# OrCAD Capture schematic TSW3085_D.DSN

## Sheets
1 SH2 - DAC PWR: size B; title: TSW3085 EVM; rev: D; note: DAC PWR
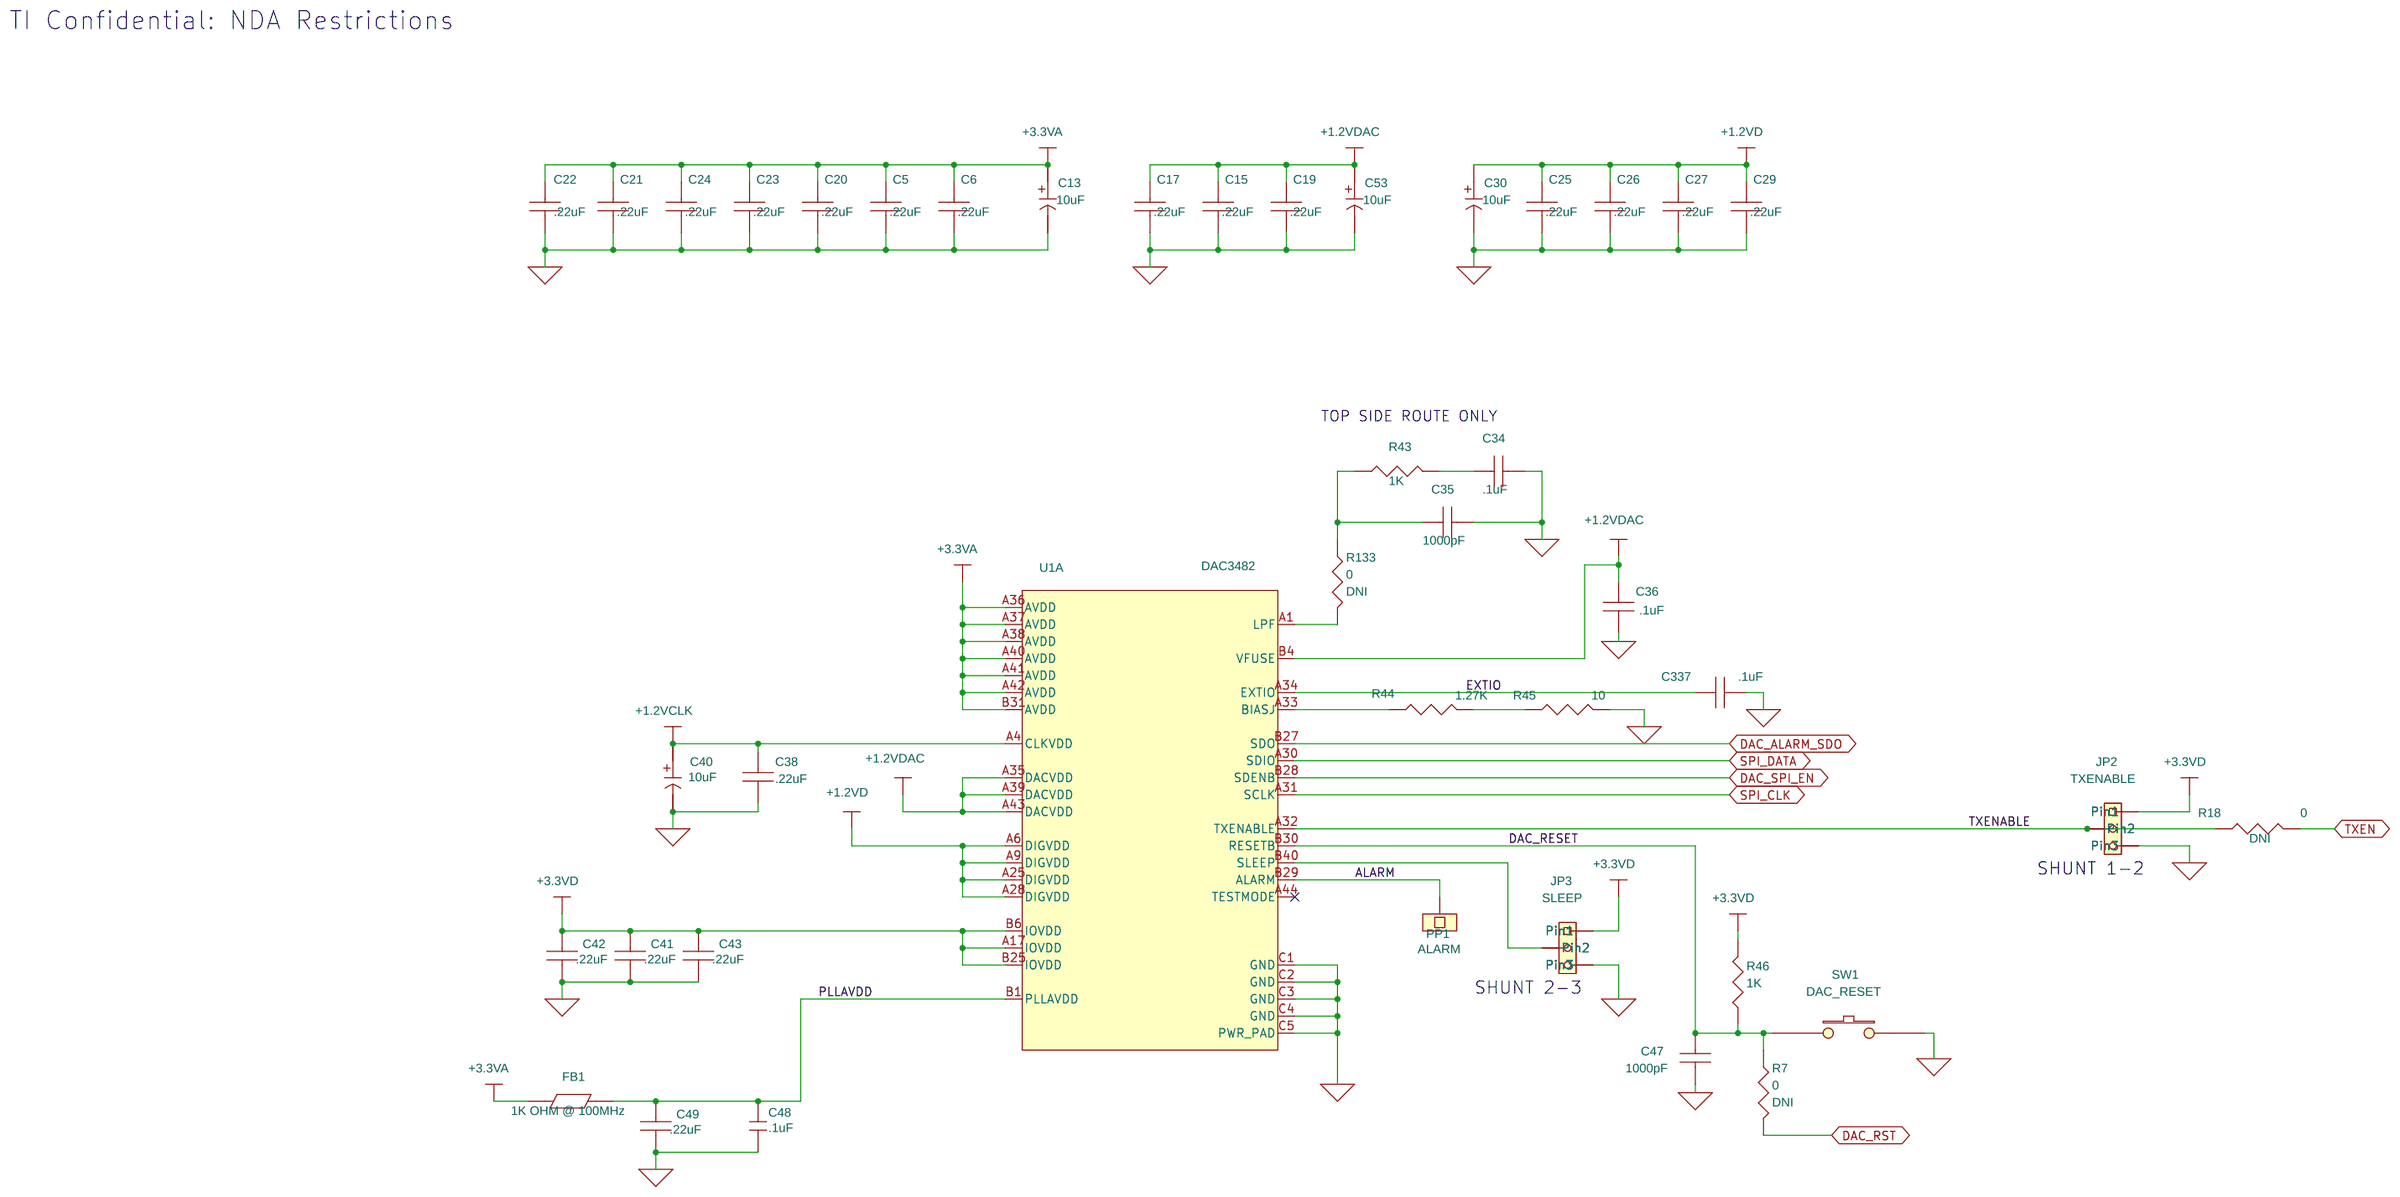
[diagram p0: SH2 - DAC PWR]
2 SH3 - CLOCK: size B; note: CLOCK
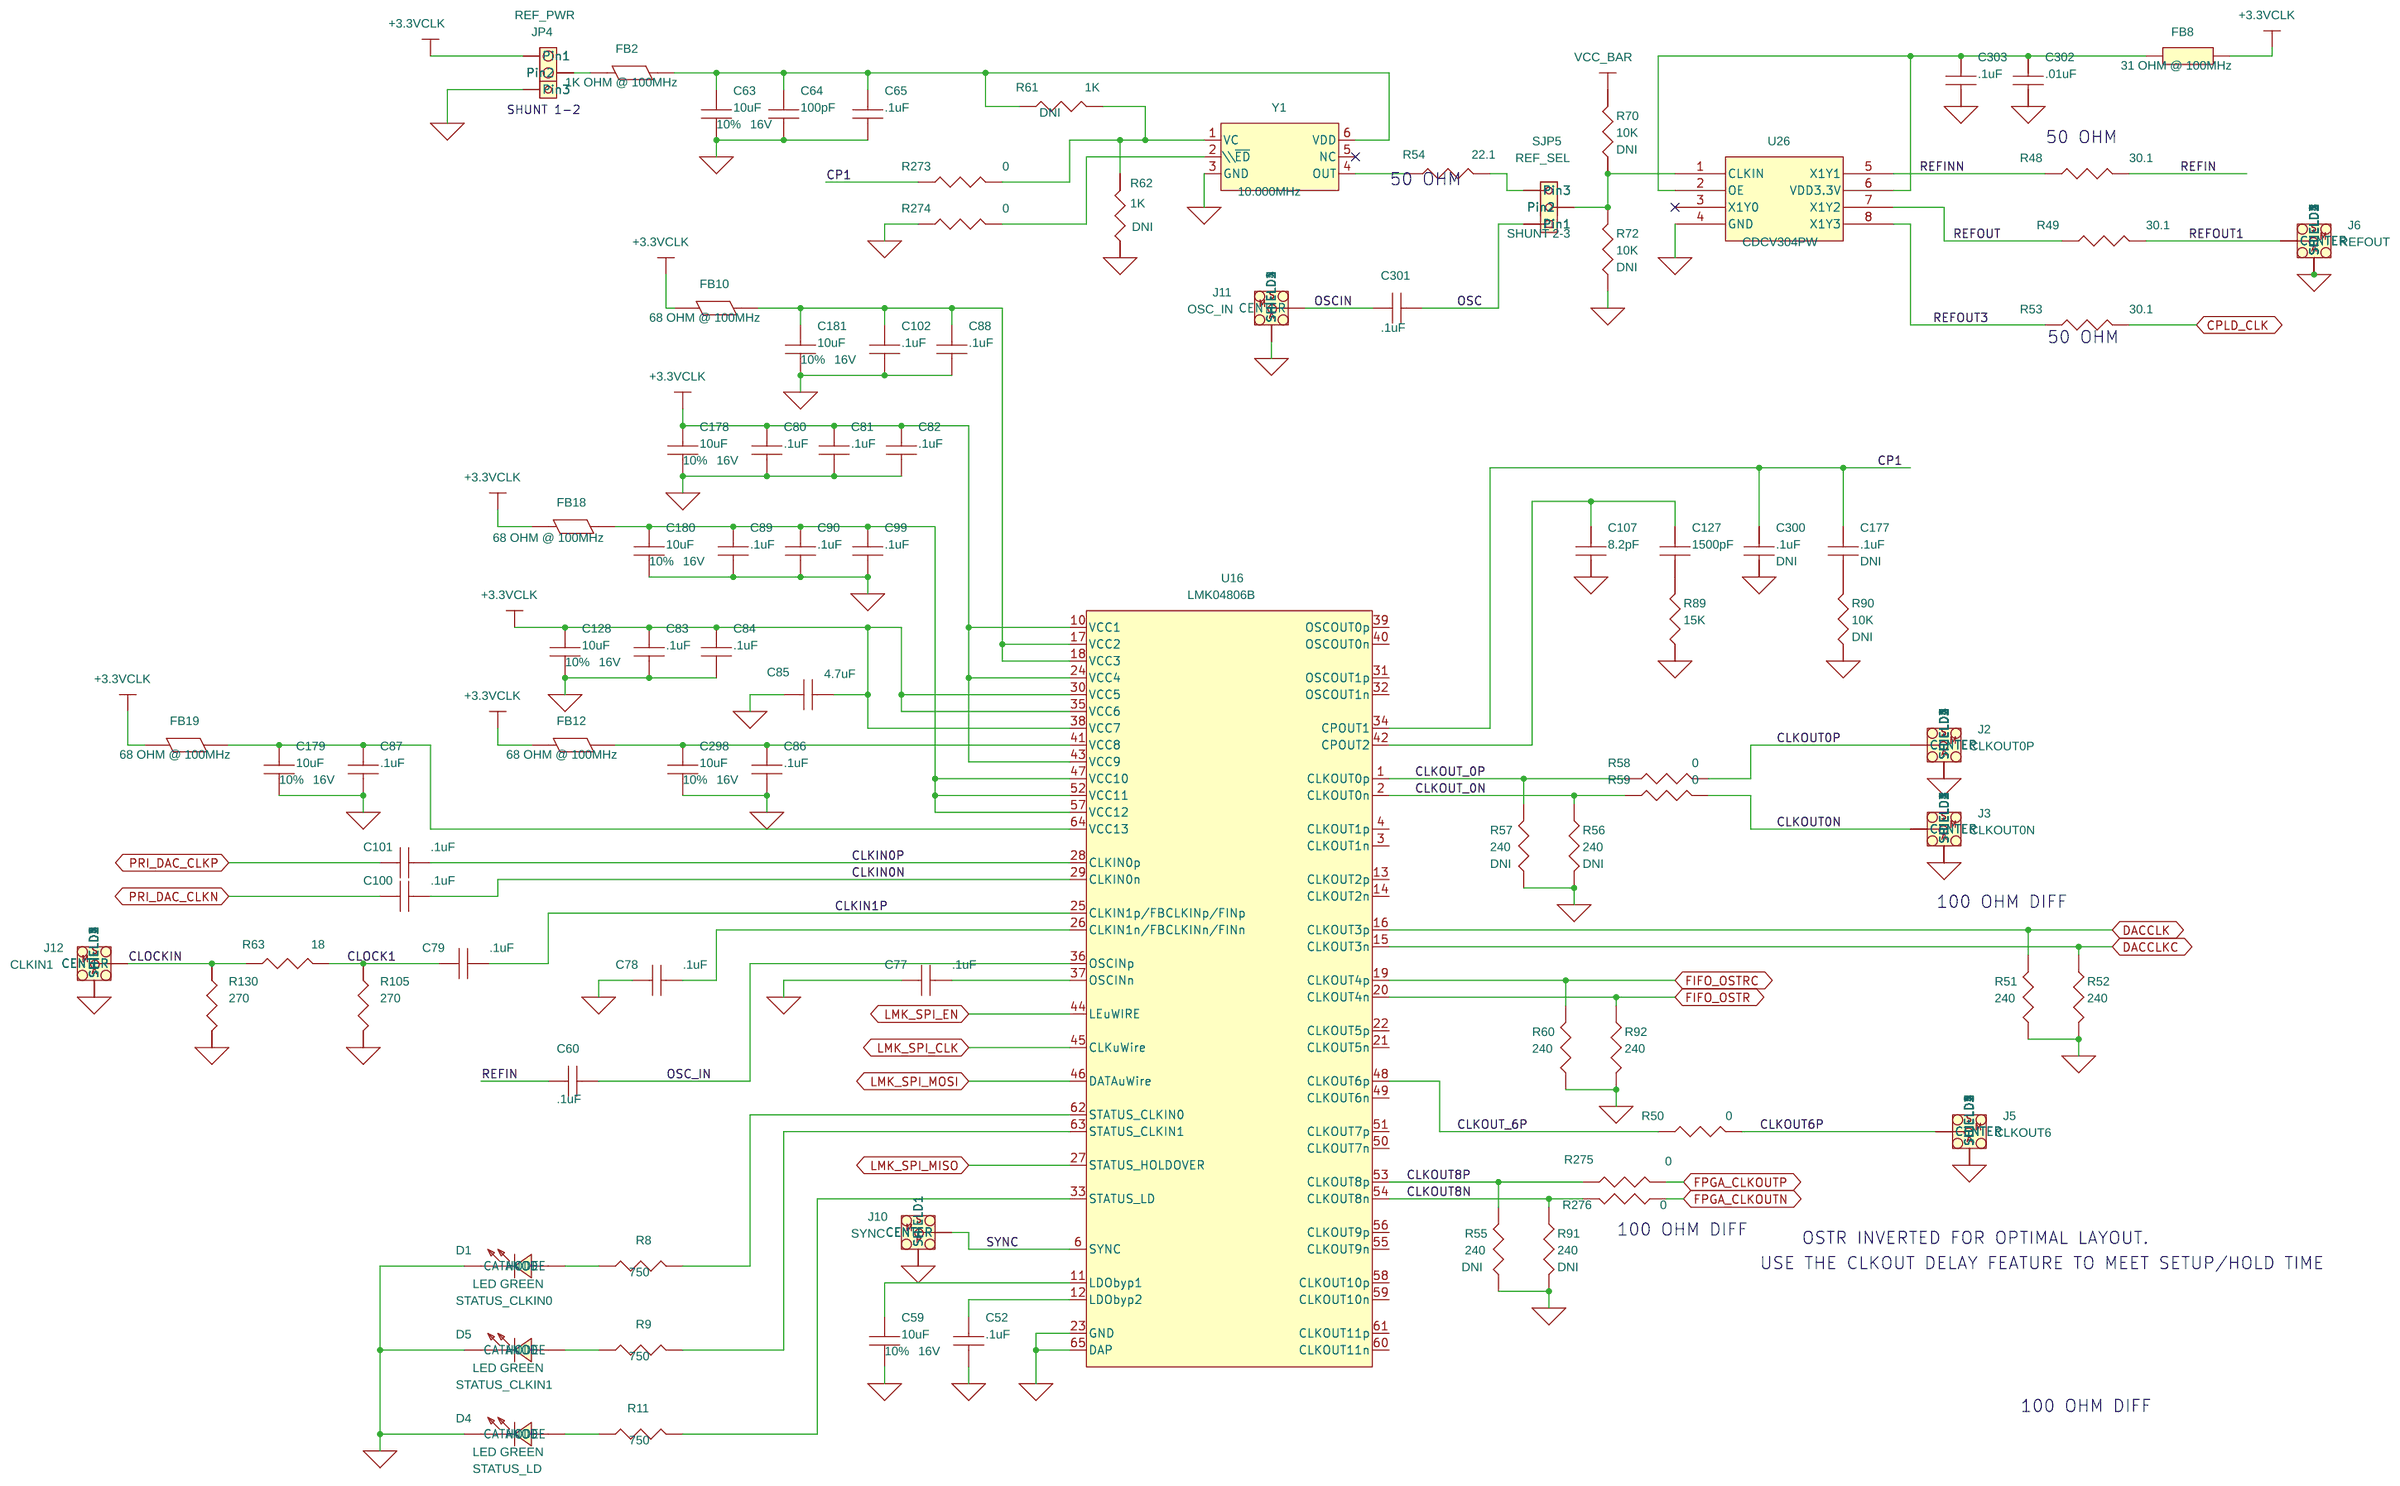
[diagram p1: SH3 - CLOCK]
3 SH5 - TX AMP & ATTENUATORS: size B; note: TX AMPLIFIER AND ATTENUATORS
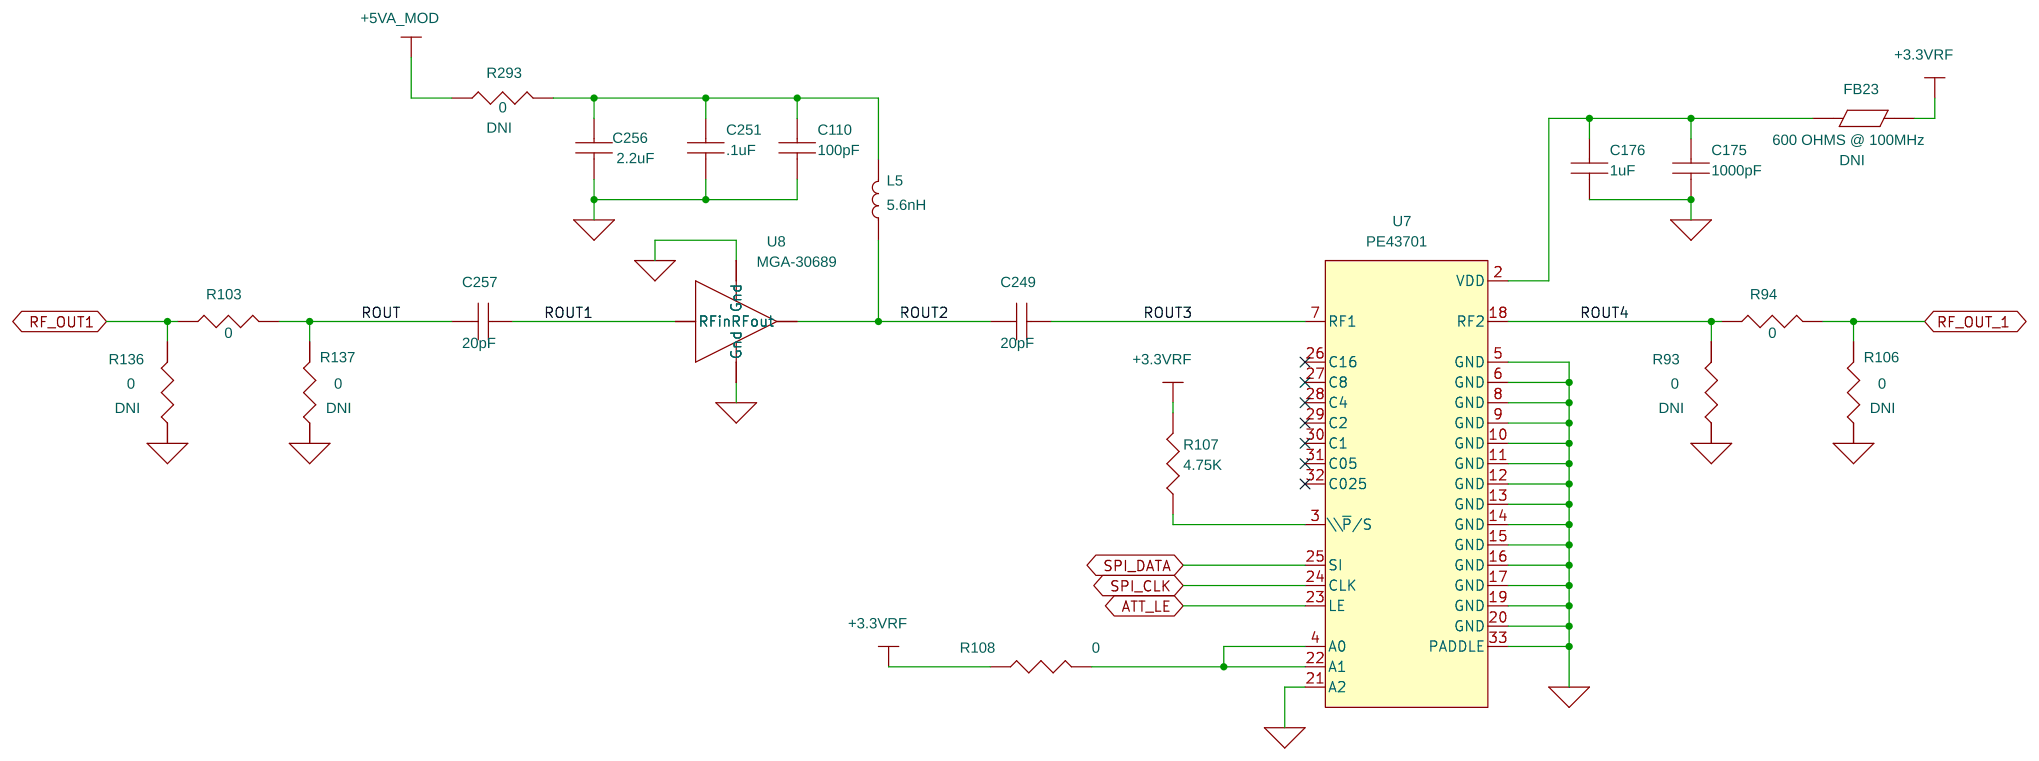
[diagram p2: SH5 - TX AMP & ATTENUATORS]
4 SH1 - DAC: size B; note: DAC
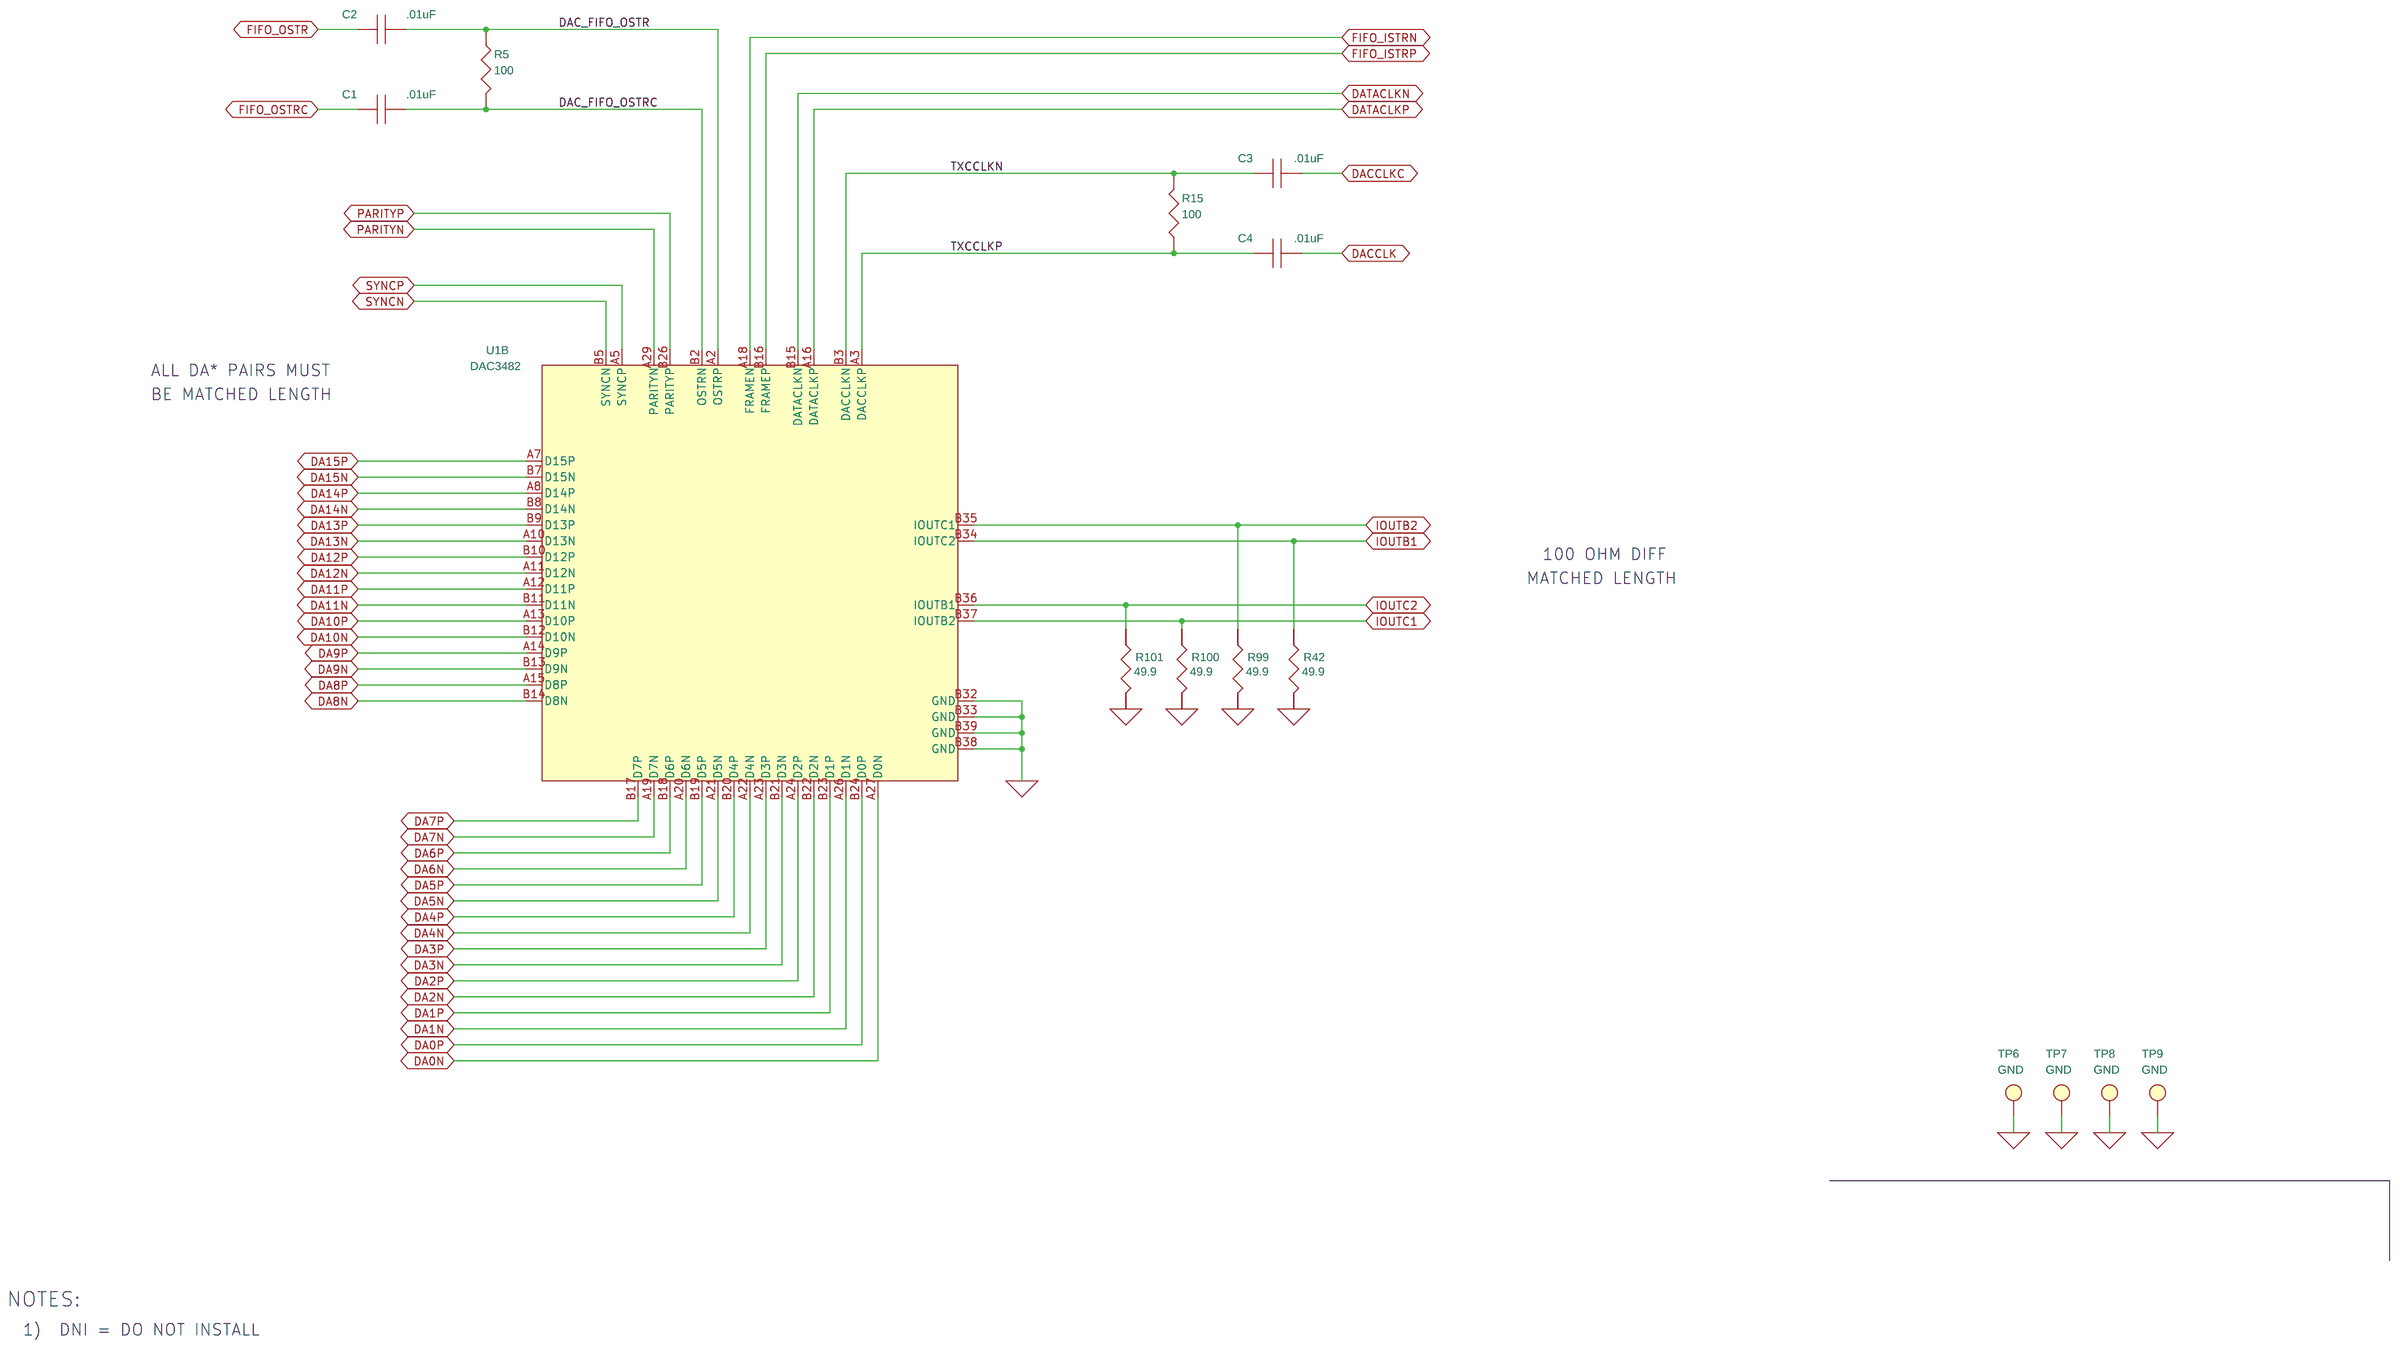
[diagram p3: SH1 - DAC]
5 SH4 - MODULATOR: size B; note: MODULATOR
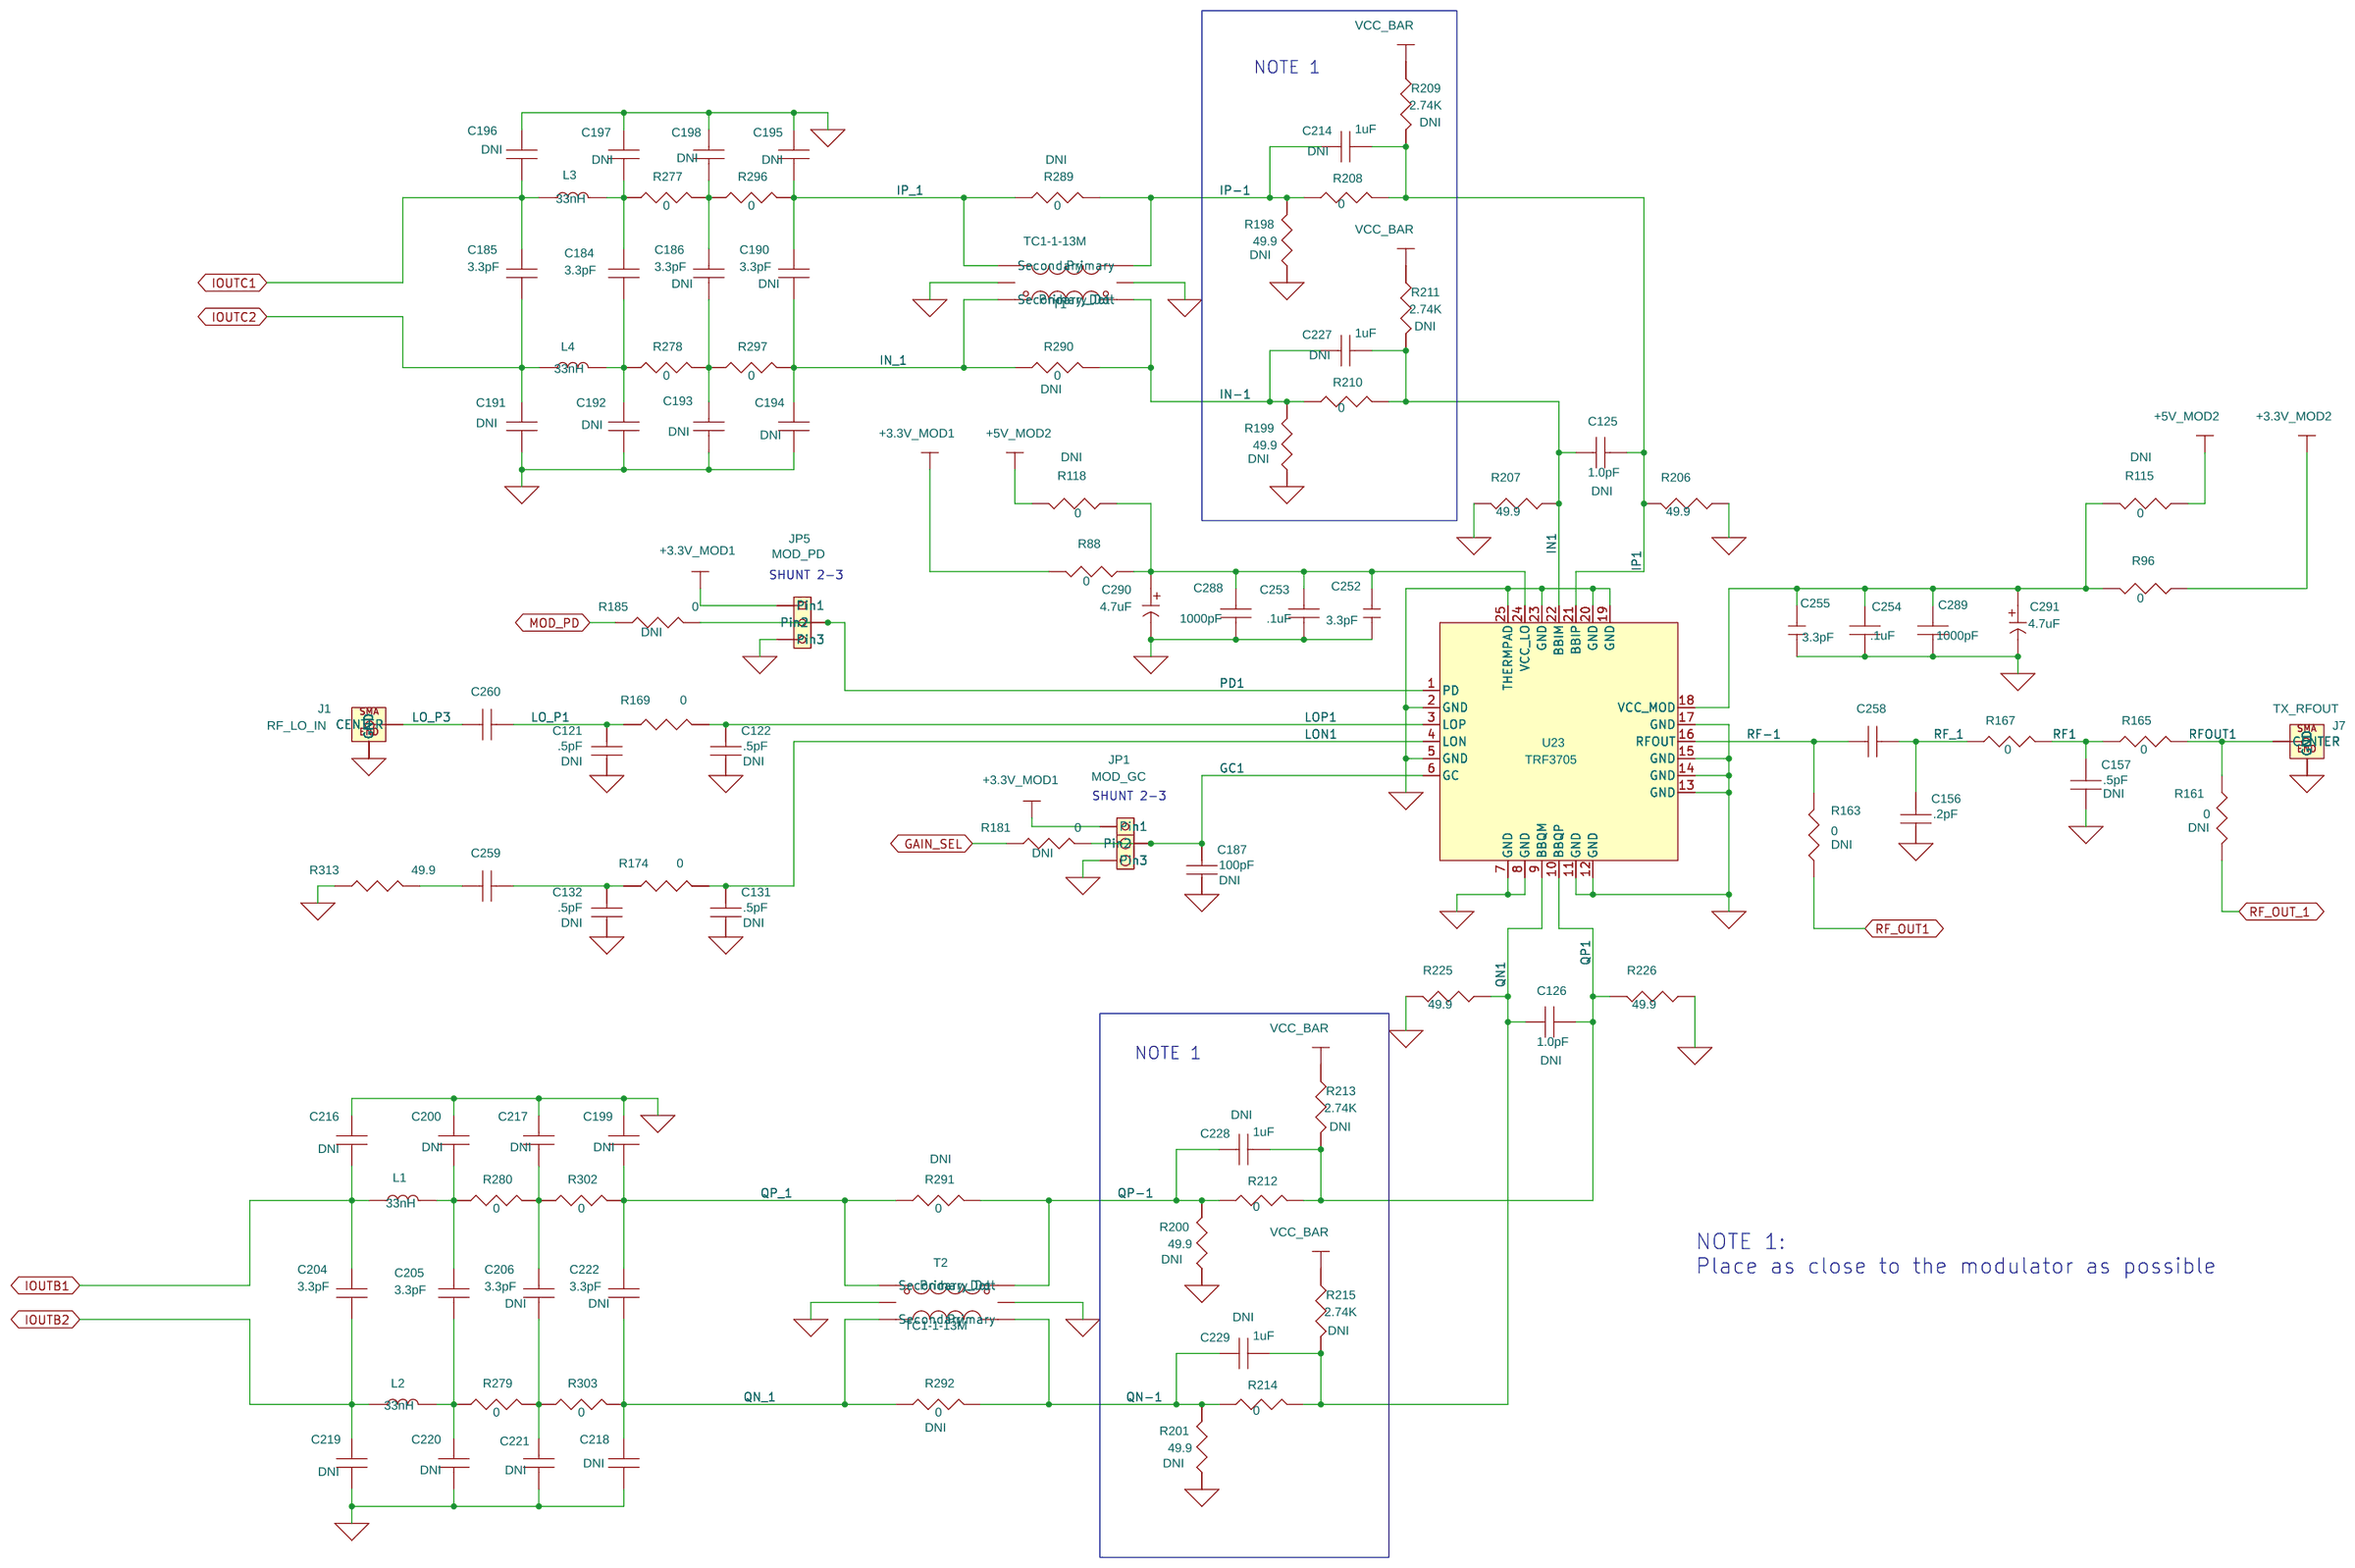
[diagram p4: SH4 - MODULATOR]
6 SH6 - INTERFACE CONTROL: size B; note: INTERFACE
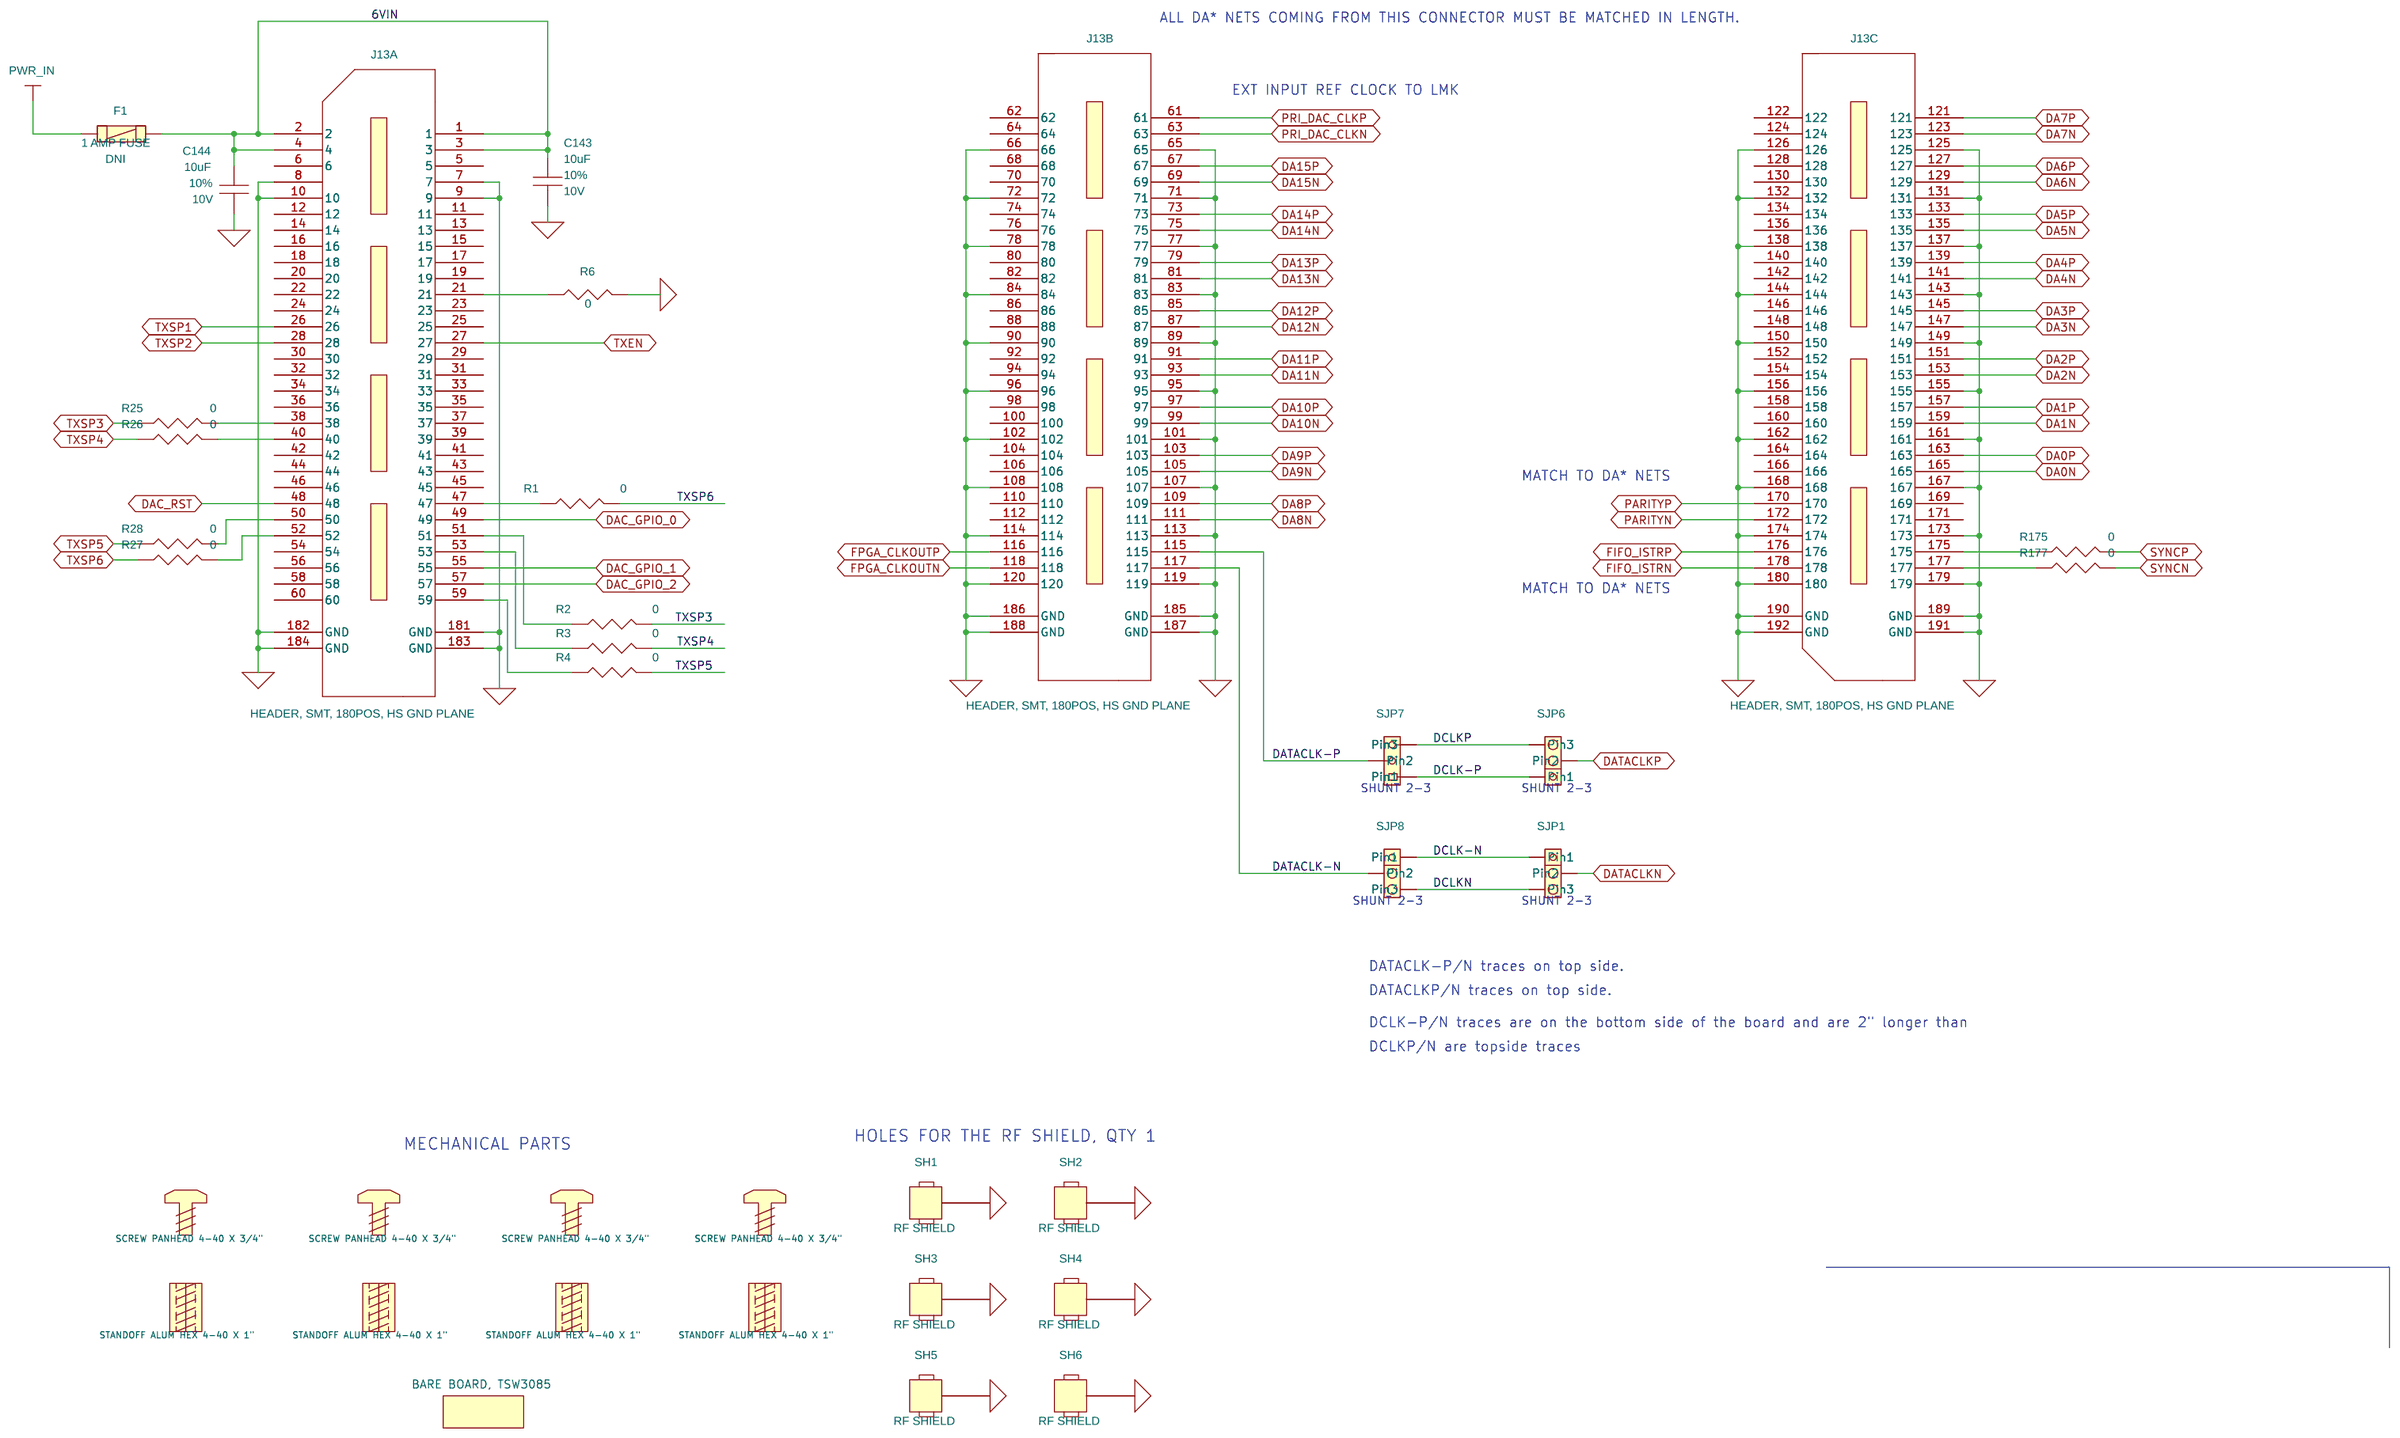
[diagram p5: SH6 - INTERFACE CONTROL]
7 SH7 - USB INTERFACE: size B; note: USB
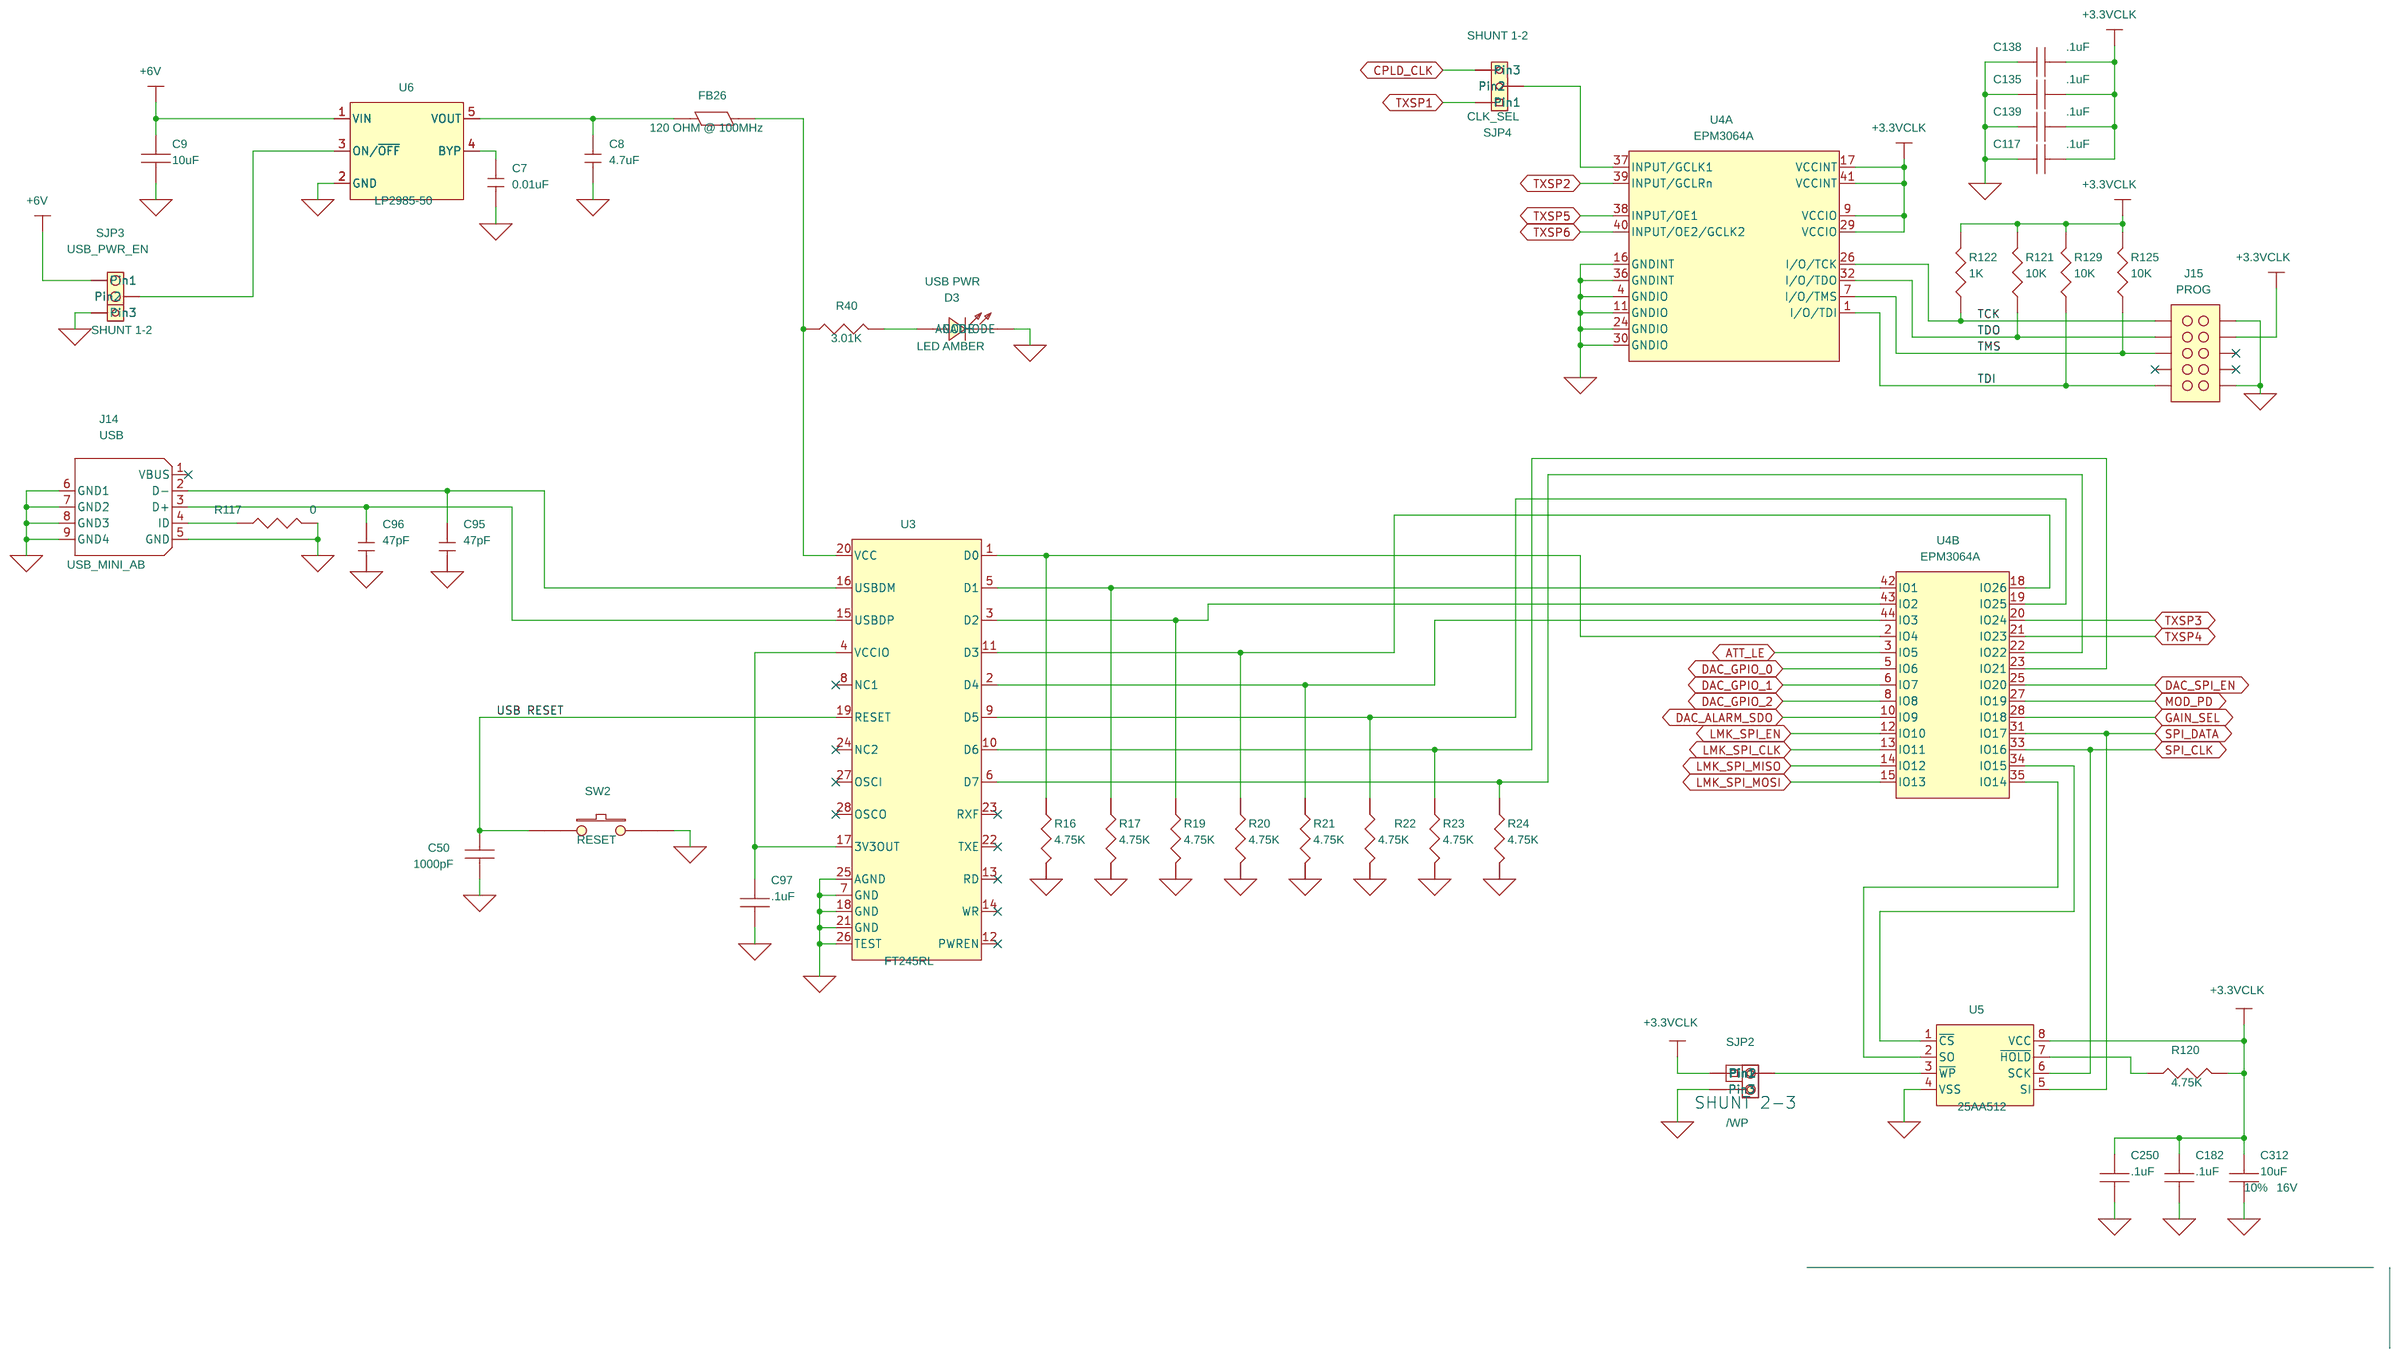
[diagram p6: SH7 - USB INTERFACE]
8 SH8 - POWER DISTRIBUTION: size B; note: DAC
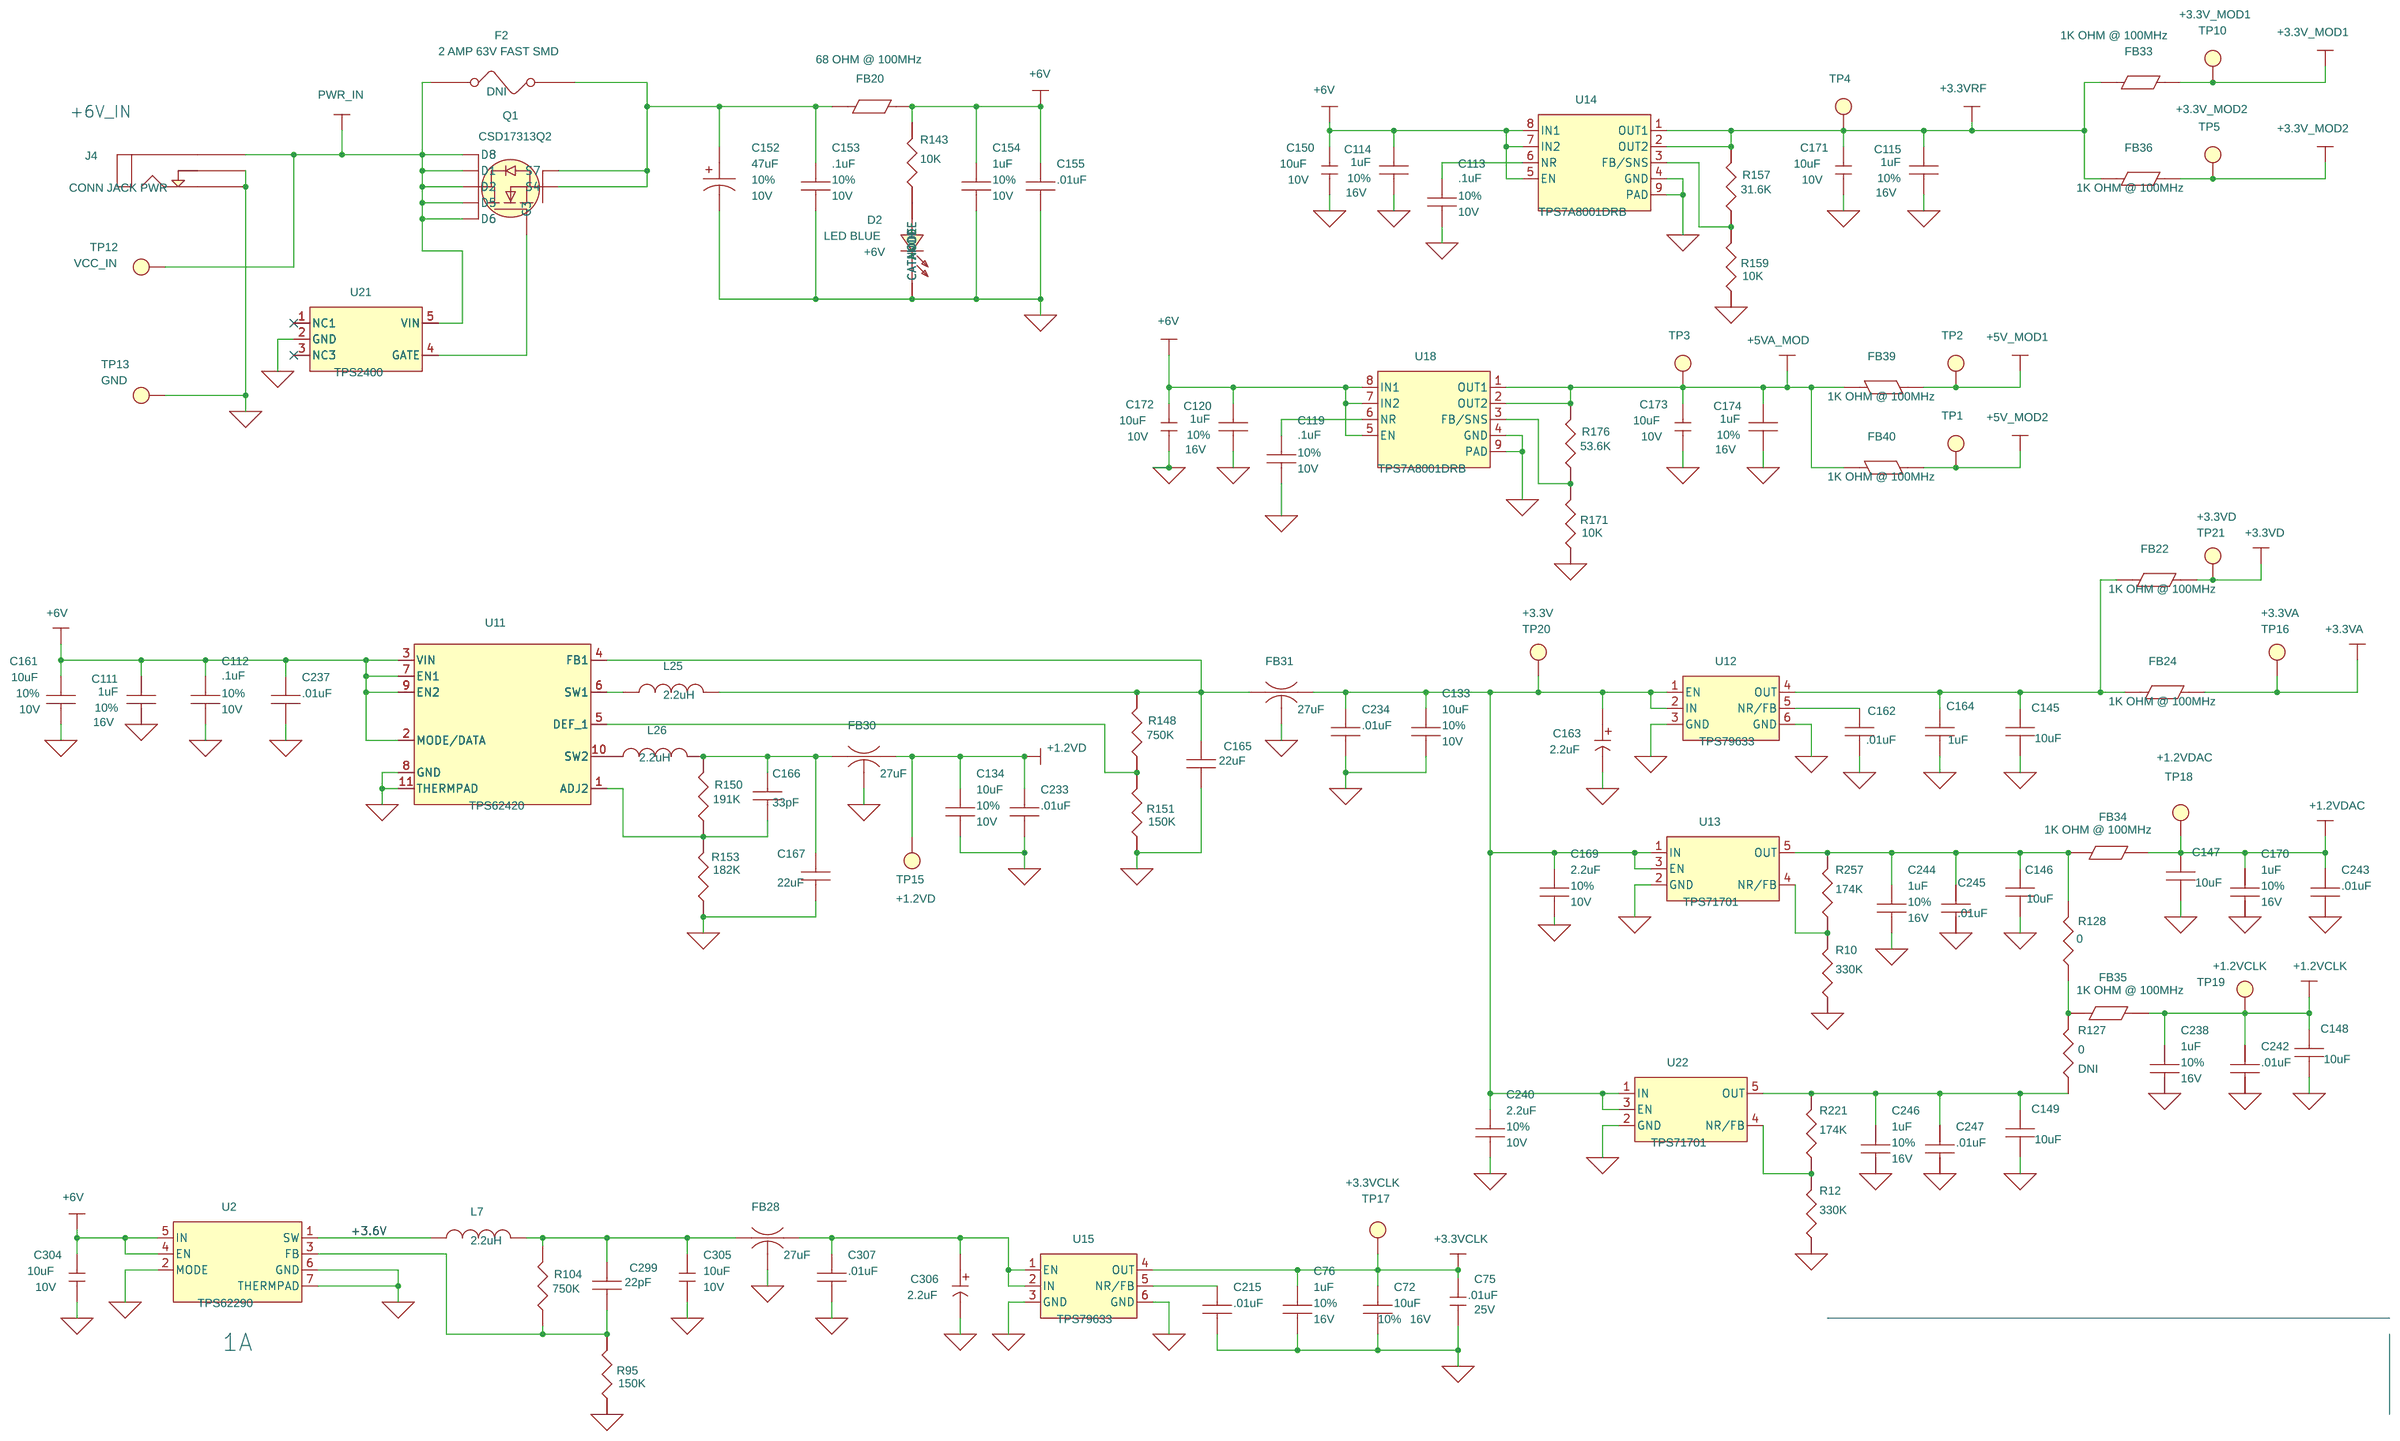
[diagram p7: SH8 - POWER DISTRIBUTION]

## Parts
sheet SH1 - DAC
C1  .01uF  [0402]
C2  .01uF  [0402]
C3  .01uF  [0402]
C4  .01uF  [0402]
R5  100  [0402]
R15  100  [0402]
R42  49.9  [0201]
R99  49.9  [0201]
R100  49.9  [0201]
R101  49.9  [0201]
TP6  TEST POINT, BLK  [testpoint_62dia]
TP7  TEST POINT, BLK  [testpoint_62dia]
TP8  TEST POINT, BLK  [testpoint_62dia]
TP9  TEST POINT, BLK  [testpoint_62dia]
U1  DAC3482  [WQFN_88_354X354_0P60MM]  (sections A,B)
sheet SH2 - DAC PWR
C5  .22uF  [0201]
C6  .22uF  [0201]
C13  10uF  [TANT_A]
C15  .22uF  [0201]
C17  .22uF  [0201]
C19  .22uF  [0201]
C20  .22uF  [0201]
C21  .22uF  [0201]
C22  .22uF  [0201]
C23  .22uF  [0201]
C24  .22uF  [0201]
C25  .22uF  [0201]
C26  .22uF  [0201]
C27  .22uF  [0201]
C29  .22uF  [0201]
C30  10uF  [TANT_A]
C34  .1uF  [0402]
C35  1000pF  [0402]
C36  .1uF  [0402]
C38  .22uF  [0201]
C40  10uF  [TANT_A]
C41  .22uF  [0201]
C42  .22uF  [0201]
C43  .22uF  [0201]
C47  1000pF  [0402]
C48  .1uF  [0201]
C49  .22uF  [0201]
C53  10uF  [TANT_A]
C337  .1uF  [0402]
FB1  1K OHM @ 100MHz  [1806]
JP2  HEADER, 3POS  [HDR_THVT_1x3_100_M]
JP3  HEADER, 3POS  [HDR_THVT_1x3_100_M]
PP1  PROBE POINT  [PROBE_POINT_30PAD]
R7  0  [0402]
R18  0  [0402]
R43  1K  [0402]
R44  1.27K  [0402]
R45  10  [0402]
R46  1K  [0402]
R133  0  [0402]
SW1  SW PUSHBUTTON  [SW_RESET_PTS635]
Z_SH-H2  SHUNT-HEADER
Z_SH-H3  SHUNT-HEADER
sheet SH3 - CLOCK
C52  .1uF  [0402]
C59  10uF  [0805]
C60  .1uF  [0402]
C63  10uF  [1206]
C64  100pF  [0402]
C65  .1uF  [0402]
C77  .1uF  [0402]
C78  .1uF  [0402]
C79  .1uF  [0402]
C80  .1uF  [0402]
C81  .1uF  [0402]
C82  .1uF  [0402]
C83  .1uF  [0402]
C84  .1uF  [0402]
C85  4.7uF  [0402]
C86  .1uF  [0402]
C87  .1uF  [0402]
C88  .1uF  [0402]
C89  .1uF  [0402]
C90  .1uF  [0402]
C99  .1uF  [0402]
C100  .1uF  [0402]
C101  .1uF  [0402]
C102  .1uF  [0402]
C107  8.2pF  [0402]
C127  1500pF  [0402]
C128  10uF  [1206]
C177  .1uF  [0402]
C178  10uF  [1206]
C179  10uF  [1206]
C180  10uF  [1206]
C181  10uF  [1206]
C298  10uF  [1206]
C300  .1uF  [0402]
C301  .1uF  [0402]
C302  .01uF  [0402]
C303  .1uF  [0402]
D1  LED GREEN  [LED_0805]
D4  LED GREEN  [LED_0805]
D5  LED GREEN  [LED_0805]
FB2  1K OHM @ 100MHz  [1806]
FB8  31 OHM @ 100MHz  [0805]
FB10  68 OHM @ 100MHz  [1206]
FB12  68 OHM @ 100MHz  [1206]
FB18  68 OHM @ 100MHz  [1206]
FB19  68 OHM @ 100MHz  [1206]
J2  SMA THRU HOLE R/A  [SMA_THRT_276X276]
J3  SMA THRU HOLE R/A  [SMA_THRT_276X276]
J5  SMA THRU HOLE R/A  [SMA_THRT_276X276]
J6  SMA THRU HOLE R/A  [SMA_THRT_276X276]
J10  SMP_PCB_SMT  [smp_b120]
J11  SMA THRU HOLE R/A  [SMA_THRT_276X276]
J12  SMA THRU HOLE  [SMA_THVT_320x320]
JP4  HEADER, 3POS  [HDR_THVT_1x3_100_M]
R8  750  [0603]
R9  750  [0603]
R11  750  [0603]
R48  30.1  [0402]
R49  30.1  [0402]
R50  0  [0402]
R51  240  [0402]
R52  240  [0402]
R53  30.1  [0201]
R54  22.1  [0402]
R55  240  [0402]
R56  240  [0402]
R57  240  [0402]
R58  0  [0402]
R59  0  [0402]
R60  240  [0402]
R61  1K  [0402]
R62  1K  [0402]
R63  18  [0402]
R70  10K  [0402]
R72  10K  [0402]
R89  15K  [0402]
R90  10K  [0402]
R91  240  [0402]
R92  240  [0402]
R105  270  [0402]
R130  270  [0402]
R273  0  [0402]
R274  0  [0402]
R275  0  [0402]
R276  0  [0402]
SJP5  SOLDER JUMPER, 0402  [SMD_JUMPER_L_0402]
U16  LMK04806B  [QFN_64_360X360_0P50MM_SQA64]
U26  CDCV304PW  [TSSOP_8_177x122_26]
Y1  10.000MHz  [OSC_6_SM_295X205_100_CUSTOM]
Z_SH-H4  SHUNT-HEADER
Z_SH-J31  SHUNT-JUMPER-0402
sheet SH4 - MODULATOR
C121  .5pF  [0402]
C122  .5pF  [0402]
C125  1.0pF  [0402]
C126  1.0pF  [0402]
C131  .5pF  [0402]
C132  .5pF  [0402]
C156  .2pF  [0402]
C157  .5pF  [0402]
C184  3.3pF  [0402]
C185  3.3pF  [0402]
C186  3.3pF  [0402]
C187  100pF  [0402]
C190  3.3pF  [0402]
C191  CAP NP_1  [0402]
C192  CAP NP_1  [0402]
C193  CAP NP_1  [0402]
C194  CAP NP_1  [0402]
C195  CAP NP_1  [0402]
C196  CAP NP_1  [0402]
C197  CAP NP_1  [0402]
C198  CAP NP_1  [0402]
C199  CAP NP_1  [0402]
C200  CAP NP_1  [0402]
C204  3.3pF  [0402]
C205  3.3pF  [0402]
C206  3.3pF  [0402]
C214  1uF  [0402]
C216  CAP NP_1  [0402]
C217  CAP NP_1  [0402]
C218  CAP NP_1  [0402]
C219  CAP NP_1  [0402]
C220  CAP NP_1  [0402]
C221  CAP NP_1  [0402]
C222  3.3pF  [0402]
C227  1uF  [0402]
C228  1uF  [0402]
C229  1uF  [0402]
C252  3.3pF  [0402]
C253  .1uF  [0402]
C254  .1uF  [0402]
C255  3.3pF  [0402]
C258  6.8pF  [0402]
C259  47pF  [0402]
C260  47pF  [0402]
C288  1000pF  [0402]
C289  1000pF  [0402]
C290  4.7uF  [tant_a]
C291  4.7uF  [tant_a]
J1  SMA END LAUNCH  [SMA_SMEL_DUAL_PSF-S01_250x215]
J7  SMA END LAUNCH  [SMA_SMEL_DUAL_PSF-S01_250x215]
JP1  HEADER, 3POS  [HDR_THVT_1x3_100_M]
JP5  HEADER, 3POS  [HDR_THVT_1x3_100_M]
L1  33nH  [0402]
L2  33nH  [0402]
L3  33nH  [0402]
L4  33nH  [0402]
R88  0  [0603]
R96  0  [0603]
R115  0  [0603]
R118  0  [0603]
R161  0  [0402]
R163  0  [0402]
R165  0  [0402]
R167  0  [0402]
R169  0  [0402]
R174  0  [0402]
R181  0  [0402]
R185  0  [0402]
R198  49.9  [0402]
R199  49.9  [0402]
R200  49.9  [0402]
R201  49.9  [0402]
R206  49.9  [0402]
R207  49.9  [0402]
R208  0  [0402]
R209  2.74K  [0402]
R210  0  [0402]
R211  2.74K  [0402]
R212  0  [0402]
R213  2.74K  [0402]
R214  0  [0402]
R215  2.74K  [0402]
R225  49.9  [0402]
R226  49.9  [0402]
R277  0  [0402]
R278  0  [0402]
R279  0  [0402]
R280  0  [0402]
R289  0  [0603]
R290  0  [0603]
R291  0  [0603]
R292  0  [0603]
R296  0  [0402]
R297  0  [0402]
R302  0  [0402]
R303  0  [0402]
R313  49.9  [0402]
T1  TC1-1-13M  [XFMR_MINICIRCUITS_AT224_1]
T2  TC1-1-13M  [XFMR_MINICIRCUITS_AT224_1]
U23  TRF3705  [QFN_24_163x163_0p50mm_pwrpad]
Z_SH-H14  SHUNT-HEADER
Z_SH-H16  SHUNT-HEADER
sheet SH5 - TX AMP & ATTENUATORS
C110  100pF  [0402]
C175  1000pF  [0402]
C176  1uF  [0603]
C249  20pF  [0402]
C251  .1uF  [0402]
C256  2.2uF  [0805]
C257  20pF  [0402]
FB23  600 OHMS @ 100MHz  [0603]
L5  5.6nH  [0402]
R93  0  [0402]
R94  0  [0402]
R103  0  [0402]
R106  0  [0402]
R107  4.75K  [0402]
R108  0  [0402]
R136  0  [0402]
R137  0  [0402]
R293  0  [0603]
U7  PE43701  [QFN_32_197X197_20_PWRPAD]
U8  MGA-30689  [SOT_89_4321]
sheet SH6 - INTERFACE CONTROL
C143  10uF  [0805]
C144  10uF  [0805]
F1  1 AMP FUSE  [NANO_SMF]
J13  HEADER, SMT, 180POS, HS GND PLANE  [CON_SMVT_180POS_QTH_SAMTEC_RT1]  (sections A,B,C)
R1  0  [0402]
R2  0  [0402]
R3  0  [0402]
R4  0  [0402]
R6  0  [0402]
R25  0  [0402]
R26  0  [0402]
R27  0  [0402]
R28  0  [0402]
R175  0  [0402]
R177  0  [0402]
SH1  RF SHIELD  [MFG053_PTH]
SH2  RF SHIELD  [MFG053_PTH]
SH3  RF SHIELD  [MFG053_PTH]
SH4  RF SHIELD  [MFG053_PTH]
SH5  RF SHIELD  [MFG053_PTH]
SH6  RF SHIELD  [MFG053_PTH]
SJP1  SOLDER JUMPER, 0603  [JUMPER_SMD_3POS_0402]
SJP6  SOLDER JUMPER, 0603  [JUMPER_SMD_3POS_0402]
SJP7  SOLDER JUMPER, 0603  [JUMPER_SMD_3POS_0402]
SJP8  SOLDER JUMPER, 0603  [JUMPER_SMD_3POS_0402]
Z_BOARD1  BARE BOARD, TSW3085
Z_SCREW1  SCREW PANHEAD 4-40 X 3/4"
Z_SCREW2  SCREW PANHEAD 4-40 X 3/4"
Z_SCREW3  SCREW PANHEAD 4-40 X 3/4"
Z_SCREW4  SCREW PANHEAD 4-40 X 3/4"
Z_SH-H17  SHUNT-JUMPER-0603
Z_SH-H18  SHUNT-JUMPER-0603
Z_SH-H19  SHUNT-JUMPER-0603
Z_SH-H20  SHUNT-JUMPER-0603
Z_STANDOFF1  STANDOFF ALUM HEX 4-40 X 1"
Z_STANDOFF2  STANDOFF ALUM HEX 4-40 X 1"
Z_STANDOFF3  STANDOFF ALUM HEX 4-40 X 1"
Z_STANDOFF4  STANDOFF ALUM HEX 4-40 X 1"
sheet SH7 - USB INTERFACE
C7  0.01uF  [0603]
C8  4.7uF  [0603]
C9  10uF  [0805]
C50  1000pF  [0402]
C95  47pF  [0402]
C96  47pF  [0402]
C97  .1uF  [0402]
C117  .1uF  [0402]
C135  .1uF  [0402]
C138  .1uF  [0402]
C139  .1uF  [0402]
C182  .1uF  [0402]
C250  .1uF  [0402]
C312  10uF  [1206]
D3  LED AMBER  [LED_0805]
FB26  120 OHM @ 100MHz  [1206]
J14  USB_MINI_AB  [CON_SMRT_USBMNE20_F]
J15  HTSW-105-07-G-D  [HDR_THVT_2x5_100_M]
R16  4.75K  [0402]
R17  4.75K  [0402]
R19  4.75K  [0402]
R20  4.75K  [0402]
R21  4.75K  [0402]
R22  4.75K  [0402]
R23  4.75K  [0402]
R24  4.75K  [0402]
R40  3.01K  [0402]
R117  0  [0603]
R120  4.75K  [0402]
R121  10K  [0402]
R122  1K  [0402]
R125  10K  [0402]
R129  10K  [0402]
SJP2  SOLDER JUMPER, 0402  [SMD_JUMPER_L_0402]
SJP3  SOLDER JUMPER, 0603  [JUMPER_SMD_L_0603]
SJP4  SOLDER JUMPER, 0402  [SMD_JUMPER_L_0402]
SW2  SW PUSHBUTTON  [SW_RESET_PTS635]
U3  FT245RL  [ssop_28_413x220_26]
U4  EPM3064A  [TQFP_44_39X39_32]  (sections A,B)
U5  25AA512  [SO_8_210X212_50]
U6  LP2985-50  [SOT_5_120X69_37]
Z_SH-H21  SHUNT-JUMPER-0603
Z_SH-J27  SHUNT-JUMPER-0402
Z_SH-J30  SHUNT-JUMPER-0402
sheet SH8 - POWER DISTRIBUTION
C72  10uF  [1206]
C75  .01uF  [0402]
C76  1uF  [0603]
C111  1uF  [0603]
C112  .1uF  [0402]
C113  .1uF  [0402]
C114  1uF  [0603]
C115  1uF  [0603]
C119  .1uF  [0402]
C120  1uF  [0603]
C133  10uF  [0805]
C134  10uF  [0805]
C145  10uF  [0805]
C146  10uF  [0805]
C147  10uF  [0805]
C148  10uF  [0805]
C149  10uF  [0805]
C150  10uF  [0805]
C152  47uF  [tant_b]
C153  .1uF  [0402]
C154  1uF  [0402]
C155  .01uF  [0402]
C161  10uF  [0805]
C162  .01uF  [0402]
C163  2.2uF  [1206]
C164  1uF  [0603]
C165  22uF  [1206]
C166  33pF  [0402]
C167  22uF  [1206]
C169  2.2uF  [0603]
C170  1uF  [0603]
C171  10uF  [0805]
C172  10uF  [0805]
C173  10uF  [0805]
C174  1uF  [0603]
C215  .01uF  [0402]
C233  .01uF  [0402]
C234  .01uF  [0402]
C237  .01uF  [0402]
C238  1uF  [0603]
C240  2.2uF  [0603]
C242  .01uF  [0402]
C243  .01uF  [0402]
C244  1uF  [0603]
C245  .01uF  [0402]
C246  1uF  [0603]
C247  .01uF  [0402]
C299  22pF  [0402]
C304  10uF  [0805]
C305  10uF  [0805]
C306  2.2uF  [TANT_A]
C307  .01uF  [0402]
D2  LED BLUE  [LED_0805]
F2  2 AMP 63V FAST SMD  [1206]
FB20  68 OHM @ 100MHz  [1206]
FB22  1K OHM @ 100MHz  [1810]
FB24  1K OHM @ 100MHz  [1810]
FB28  27uF  [1206_BEAD_NFM31P]
FB30  27uF  [1206_BEAD_NFM31P]
FB31  27uF  [1206_BEAD_NFM31P]
FB33  1K OHM @ 100MHz  [1810]
FB34  1K OHM @ 100MHz  [1810]
FB35  1K OHM @ 100MHz  [1810]
FB36  1K OHM @ 100MHz  [1810]
FB39  1K OHM @ 100MHz  [1810]
FB40  1K OHM @ 100MHz  [1810]
J4  CONN JACK PWR  [CON_RAPC722_JACK_THVT_3]
L7  2.2uH  [LPS3015]
L25  2.2uH  [LPS3015]
L26  2.2uH  [LPS3015]
Q1  CSD17313Q2  [SON_8_2MMX2MM_0P65MM]
R10  330K  [0402]
R12  330K  [0402]
R95  150K  [0402]
R104  750K  [0402]
R127  0  [0805]
R128  0  [0805]
R143  10K  [0603]
R148  750K  [0402]
R150  191K  [0402]
R151  150K  [0402]
R153  182K  [0402]
R157  31.6K  [0402]
R159  10K  [0402]
R171  10K  [0402]
R176  53.6K  [0402]
R221  174K  [0402]
R257  174K  [0402]
TP1  TEST POINT, RED  [testpoint_62dia]
TP2  TEST POINT, RED  [testpoint_62dia]
TP3  TEST POINT, RED  [testpoint_62dia]
TP4  TEST POINT, RED  [testpoint_62dia]
TP5  TEST POINT, RED  [testpoint_62dia]
TP10  TEST POINT, RED  [testpoint_62dia]
TP12  TEST POINT, RED  [testpoint_62dia]
TP13  TEST POINT, BLK  [testpoint_62dia]
TP15  TEST POINT, RED  [testpoint_62dia]
TP16  TEST POINT, RED  [testpoint_62dia]
TP17  TEST POINT, RED  [testpoint_62dia]
TP18  TEST POINT, RED  [testpoint_62dia]
TP19  TEST POINT, RED  [testpoint_62dia]
TP20  TEST POINT, RED  [testpoint_62dia]
TP21  TEST POINT, RED  [testpoint_62dia]
U2  TPS62290  [SON_DRV_6]
U11  TPS62420  [SON_DRC_10]
U12  TPS79633  [SOT_223_6_TG]
U13  TPS71701  [SC70_DCK_G5]
U14  TPS7A8001DRB  [SON_8_124x124_pwrpad_DRB]
U15  TPS79633  [SOT_223_6_TG]
U18  TPS7A8001DRB  [SON_8_124x124_pwrpad_DRB]
U21  TPS2400  [DBV5]
U22  TPS71701  [SC70_DCK_G5]

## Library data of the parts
C1-C4 C302 = CAP_NP_0: Mfr_Name: KEMET; Mfr_Part_Number: C0402C103J3RACTU; TOL: 5%; VOLTAGE: 25V
R5 R15 = R_0: Mfr_Name: PANASONIC; Mfr_Part_Number: ERJ-2RKF1000X; TOL: 1%
R42 R99-R101 = Res_0603: Mfr_Name: PANASONIC; Mfr_Part_Number: ERJ-1GEF49R9C; TOL: 1%
TP6-TP9 TP13 = TESTLOOP_BLACK: Mfr_Name: KEYSTONE; Mfr_Part_Number: 5011; TI_SILKTEXT: GND
U1 = DAC3482: Mfr_Part_Number: DAC3482IRKDT
C5 C6 C15 C17 C19-C27 C29 C38 C41-C43 C49 = CAP_NP_0: Mfr_Name: TAIYO YUDEN; Mfr_Part_Number: JMK063BJ224MP-F; TOL: 20%; VOLTAGE: 16V
C13 C30 C40 C53 = CAP_POL-B_10uF_10V: CLASS: DISCRETE; Mfr_Name: KEMET; Mfr_Part_Number: T491A106M016AT
C34 C36 C65 C182 C250 C251 C253 C254 C301 C303 C337 = CAP_NP_0: Mfr_Name: MURATA; Mfr_Part_Number: GRM155R71C104KA88D; TOL: 10%; VOLTAGE: 10V
C35 C47 C175 C288 C289 = CAP_NP_0: Mfr_Name: AVX; Mfr_Part_Number: 04025C102JAT2A; TOL: 5%; VOLTAGE: 50V
C48 = CAP0402: Mfr_Name: TAIYO YUDEN; Mfr_Part_Number: JMK063BJ104KP-F; TOL: -20%/+80%; Voltage: 16V
FB1 FB2 = FERRITE_BEAD_0402_H: Mfr_Name: MURATA; Mfr_Part_Number: BLM41PG102SN1L
JP2 = Jumper_1x3_100_0: Mfr_Name: SAMTEC; Mfr_Part_Number: HMTSW-103-07-G-S-.230; TI_Silktext: TXENABLE
JP3 = Jumper_1x3_100_0: Mfr_Name: SAMTEC; Mfr_Part_Number: HMTSW-103-07-G-S-.230; TI_Silktext: SLEEP
PP1 = PROBE_POINT: Note: DNI; TI_Silktext: ALARM
R7 R18 R133 = Res_0402_Zero: Mfr_Part_Number: ERJ-2GE0R00X_DNI; Note: DNI
R43 = R_0: Mfr_Name: PANASONIC; Mfr_Part_Number: ERJ-2RKF1001X; TOL: 1%
R44 = R_0: Mfr_Name: PANASONIC; Mfr_Part_Number: ERJ-2RKF1271X; TOL: 1%
R45 = R_0: Mfr_Name: Vishay/Dale; Mfr_Part_Number: CRCW040210R0FKED; TOL: 1%
R46 R122 = R_0: Mfr_Name: Panasonic; Mfr_Part_Number: ERJ-2RKF1001X; PART_NUMBER: Panasonic ERJ-2RKF1001X; TOL: 1%
SW1 = SW_PUSHBUTTON_1: CLASS: DISCRETE; Manufacturer: C & K Switch; Mfr_Name: ITT Industries/C&K Div; Mfr_Part_Number: PTS635SL43; PART_NUMBER: PTS635SL43; TI_Silktext: DAC_RESET
Z_SH-H2-Z_SH-H4 Z_SH-H14 Z_SH-H16 = SHUNT-HEADER: Mfr_Name: KELTRON; Note: OR EQUIVALENT
C52 C60 C77-C84 C86-C90 C99-C102 C117 C135 C138 C139 = CAPACITOR_NP_1: Mfr_Name: MURATA; Mfr_Part_Number: GRM155R71C104KA88D; TOL: 10%
C59 = CAP_NP_2: CLASS: DISCRETE; Mfr_Name: MURATA; Mfr_Part_Number: GRM21BR61C106KE15L; TOL: 10%; VOLTAGE: 16V
C63 C312 = CAP_NP_1: CLASS: DISCRETE; Mfr_Name: MURATA; Mfr_Part_Number: GRM31CR61E106KA12L; TOL: 10%; VOLTAGE: 16V
C64 C110 = CAP_NP_0: Mfr_Name: MURATA; Mfr_Part_Number: GRM1555C1H101JZ01B; TOL: 5%; VOLTAGE: 50V
C85 = CAPACITOR_NP_1: Mfr_Name: TDK; Mfr_Part_Number: C1005X5R0J475M; TOL: 20%; Voltage: 6.3V
C107 = CAP_NP_0: Mfr_Name: AVX; Mfr_Part_Number: 04025A8R2CAT2A; TOL: 10%; VOLTAGE: 16V
C127 = CAP_NP_0: Mfr_Name: AVX; Mfr_Part_Number: 04025C152JAT2A; TOL: 5%; VOLTAGE: 50V
C72 C128 C178-C181 C298 = CAP_NP_2: CLASS: DISCRETE; Mfr_Name: MURATA; Mfr_Part_Number: GRM31CR61E106KA12L; TOL: 10%; VOLTAGE: 16V
C177 C300 = CAP_NP_0: Mfr_Name: MURATA; Mfr_Part_Number: GRM155R71C104KA88D_DNI; Note: DNI; TOL: 10%; VOLTAGE: 10V
D1 = LED: Mfr_Name: PANASONIC; Mfr_Part_Number: LNJ306G5UUX; TI_Silktext: STATUS_CLKIN0
D4 = LED: Mfr_Name: PANASONIC; Mfr_Part_Number: LNJ306G5UUX; TI_Silktext: STATUS_LD
D5 = LED: Mfr_Name: PANASONIC; Mfr_Part_Number: LNJ306G5UUX; TI_Silktext: STATUS_CLKIN1
FB8 = 0805FERRITE: Mfr_Name: STEWARD; Mfr_Part_Number: HI0805Q310R-10; Note: OR EQUIVALENT
FB10 FB12 FB18 FB19 = FERRITE_BEAD_0402_H: Mfr_Name: PANASONIC; Mfr_Part_Number: EXC-ML32A680U
J2 = SMA_PCB_THVT_142-0701-201_REC: Mfr_Name: AMPHENOL CONNEX; Mfr_Part_Number: 132136; TI_Silktext: CLKOUT0P
J3 = SMA_PCB_THVT_142-0701-201_REC: Mfr_Name: AMPHENOL CONNEX; Mfr_Part_Number: 132136; TI_Silktext: CLKOUT0N
J5 = SMA_PCB_THVT_142-0701-201_REC: Mfr_Name: AMPHENOL CONNEX; Mfr_Part_Number: 132136; TI_Silktext: CLKOUT6
J6 = SMA_PCB_THVT_142-0701-201_REC: Mfr_Name: AMPHENOL CONNEX; Mfr_Part_Number: 132136; TI_Silktext: REFOUT
J10 = SMP_PLUG_SMT: Manufacturer: Molex Inc.; Manufacturer Part Number: 0853050232; Mfr_Name: Molex Inc.; Mfr_Part_Number: 0853050232; TI_Silktext: SYNC
J11 = SMA_PCB_THVT_142-0701-201_REC: Mfr_Name: AMPHENOL CONNEX; Mfr_Part_Number: 132136; TI_Silktext: OSC_IN
J12 = SMA_PCB_THVT_142-0701-201_REC: Mfr_Name: Johnson Components; Mfr_Part_Number: 142-0701-201; TI_Silktext: CLKIN1
JP4 = SMD_JUMPER_1x3: Mfr_Name: SAMTEC; Mfr_Part_Number: HMTSW-103-07-G-S-.230; TI_Silktext: REF_PWR
R8 R9 R11 = RESISTOR: CLASS: DISCRETE; Mfr_Name: DALE; Mfr_Part_Number: CRCW0603750RFKEA
R48 R49 = R_0: Mfr_Name: PANASONIC; Mfr_Part_Number: ERJ-2RKF30R1X; TOL: 1%
R50 R58 R59 R275 R276 = Res_0402_Zero_H_DNI: Mfr_Part_Number: ERJ-2GE0R00X
R51 R52 R60 R92 = Res_0402_249: Mfr_Part_Number: ERJ-2RKF2400X
R53 = R_0: Mfr_Name: PANASONIC; Mfr_Part_Number: ERJ-1GEF30R1C; TOL: 1%
R54 = Res_0402_22.1_H
R55-R57 R91 = Res_0402_249: Mfr_Part_Number: ERJ-2RKF2400X_DNI; Note: DNI
R61 R62 = Res_0402_22.1_H: Mfr_Part_Number: ERJ-2RKF1001X_DNI; Note: DNI
R63 = Res_0402_22.1_H: Mfr_Part_Number: ERJ-2RKF18R0X
R70 R72 R90 = R_1: CLASS: DISCRETE; Mfr_Name: PANASONIC; Mfr_Part_Number: ERJ-2RKF1002X_DNI; Note: DNI; TOL: 1%
R89 = R_1: CLASS: DISCRETE; Mfr_Name: PANASONIC; Mfr_Part_Number: ERJ-2RKF1502X; TOL: 1%
R105 R130 = Res_0402_49.9: Mfr_Part_Number: ERJ-2RKF2700X; TOL: 1%
R1-R4 R273 R274 = Res_0402_Zero_H_DNI
SJP5 = JUMPER_SMD_1X3: Mfr_Name: DNI; Mfr_Part_Number: DNI; Note: SHUNT 2-3; TI_Silktext: REF_SEL
U16 = LMK04806B
U26 = CDCV304PW_4: Mfr_Name: TI; TI_Supplied: YES
Y1 = OSC_6_SM_FOX_HCMOS: Mfr_Part_Number: FVXO-HC73BR-10.000000
Z_SH-J30 Z_SH-J31 = SHUNT-JUMPER-0603: Mfr_Part_Number: ERJ-2GE0R00X
C121 C122 C131 C132 = CAP_NP_2: Mfr_Name: MURATA; Mfr_Part_Number: GRM1555C1HR50CZ01D_DNI; Note: DNI; TOL: .25pF; VOLTAGE: 50V
C125 = CAP_0402: Mfr_Name: Murata; Mfr_Part_Number: GJM1555C1H1R0CB01D_DNI; Note: DNI
C126 = CAP_0402: Mfr_Name: MURATA; Mfr_Part_Number: GJM1555C1H1R0CB01D_DNI; Note: DNI
C156 = CAP_NP_2: Mfr_Name: Johanson Technology Inc; Mfr_Part_Number: 500R07S0R2BV4T; TOL: .1pF; VOLTAGE: 50V
C157 = CAP_NP_2: Mfr_Name: Taiyo Yuden; Mfr_Part_Number: UVK105CH0R5BW-F_DNI; Note: DNI; TOL: .1pF; VOLTAGE: 50V
C184 = CAP_NP_1: Mfr_Name: Murata; Mfr_Part_Number: GJM1555C1H3R3CB01D; TOL: .25pF; VOLTAGE: 50V
C185 C204 C205 = CAP_NP_1: Mfr_Name: MURATA; Mfr_Part_Number: GJM1555C1H3R3CB01D; TOL: .25pF; VOLTAGE: 50V
C186 C190 C206 C222 = CAP_NP_1: Mfr_Name: MURATA; Mfr_Part_Number: GJM1555C1H3R3CB01D_DNI; Note: DNI; TOL: .25pF; VOLTAGE: 50V
C187 = CAP_NP_2: Mfr_Name: MURATA; Mfr_Part_Number: GRM1555C1H101JZ01D_DNI; Note: DNI; TOL: 5%; VOLTAGE: 50V
C191-C200 C216-C221 = CAP_NP_1: Mfr_Name: DNI; Mfr_Part_Number: DNI; Note: DNI; TOL: .25pF; VOLTAGE: 50V
C214 C227-C229 = CAP_NP_0: Mfr_Name: AVX; Mfr_Part_Number: 0402ZD105KAT2A_DNI; Note: DNI; TOL: 10%; VOLTAGE: 10V
C252 C255 = CAP0402: Mfr_Name: Murata; Mfr_Part_Number: GRM1555C1H3R3CZ01D
C258 = CAP_NP_1: Mfr_Name: Murata; Mfr_Part_Number: GJM1555C1H6R8CB01D; TOL: .25pF; VOLTAGE: 50V
C259 C260 = CAP_NP_1: Mfr_Name: TDK CORP; Mfr_Part_Number: C1005C0G1H470G; TOL: 2%; VOLTAGE: 50V
C290 C291 = CAP_POL-B_10uF_10V: Mfr_Name: AVX; Mfr_Part_Number: TAJA475K020R; PART_NUMBER: AVX TAJA475K020R; TOL: 10%; VOLTAGE: 20V
J1 = SMA-END_JACK_142-0761-801_ROUND: Mfr_Name: Johnson Components; Mfr_Part_Number: 142-0711-821; TI_Silktext: RF_LO_IN
J7 = SMA-END_JACK_142-0761-801_ROUND: Mfr_Name: Johnson Components; Mfr_Part_Number: 142-0711-821; TI_Silktext: TX_RFOUT
JP1 = Jumper_1x3_100_0: Mfr_Name: SAMTEC; Mfr_Part_Number: HMTSW-103-07-G-S-.230; TI_Silktext: MOD_GC
JP5 = Jumper_1x3_100_0: Mfr_Name: SAMTEC; Mfr_Part_Number: HMTSW-103-07-G-S-.230; TI_Silktext: MOD_PD
L1-L4 = IND0603_0: Mfr_Name: COILCRAFT; Mfr_Part_Number: 0402CS-33NXJB; TOL: 2%
R88 R96 = R: Mfr_Name: PANASONIC; Mfr_Part_Number: ERJ-3GEY0R00V; TOL: 5%
R115 R118 R289-R293 = R: Mfr_Name: PANASONIC; Mfr_Part_Number: ERJ-3GEY0R00V_DNI; Note: DNI; TOL: 5%
R161 R163 = R: Mfr_Name: PANASONIC; Mfr_Part_Number: ERJ-2GE0R00X_DNI; Note: DNI; TOL: 5%
R108 R165 R167 R277-R280 R296 R297 R302 R303 = R: Mfr_Name: PANASONIC; Mfr_Part_Number: ERJ-2GE0R00X; TOL: 5%
R169 R174 = R_5: Mfr_Name: PANASONIC; Mfr_Part_Number: ERJ-2GE0R00X; TOL: 5%
R181 R185 = R_5: Mfr_Name: PANASONIC; Mfr_Part_Number: ERJ-2GE0R00X_DNI; Note: DNI; TOL: 5%
R198-R201 = R_5: Mfr_Name: PANASONIC; Mfr_Part_Number: ERJ-2RKF49R9X_DNI; Note: DNI; TOL: 1%
R206 R207 R225 R226 = R_5: Mfr_Name: PANASONIC; Mfr_Part_Number: ERJ-2RKF49R9X; TOL: 1%
R208 R210 R212 R214 = R_0: Mfr_Name: PANASONIC; Mfr_Part_Number: ERJ-2GE0R00X; TOL: 5%
R209 R211 R213 R215 = R_5: Mfr_Name: PANASONIC; Mfr_Part_Number: ERJ-2RKF2741X_DNI; Note: DNI; TOL: 1%
R313 = R: Mfr_Name: PANASONIC; Mfr_Part_Number: ERJ-2RKF49R9X; TOL: 1%
T1 T2 = TFMR_5_ETC1-1-13_5: Mfr_Name: Mini Circuits; Mfr_Part_Number: TC1-1-13M+
U23 = TRF3705_0: Mfr_Name: TI; Mfr_Part_Number: TRF3705IRGE
C76 C176 = CAP_NP_0: Mfr_Name: AVX; Mfr_Part_Number: 0603YC105KAT2A; TOL: 10%; VOLTAGE: 16V
C249 C257 = CAP_NP_0: Mfr_Name: MURATA; Mfr_Part_Number: GRM1555C1H200JZ01B; TOL: 5%; VOLTAGE: 50V
C256 = CAP_NP_0: Mfr_Name: TDK CORP; Mfr_Part_Number: CGJ4J2X7R1A225K; TOL: 10%; VOLTAGE: 10V
FB23 = FERRITE_BEAD_0603: Mfr_Name: MURATA; Mfr_Part_Number: BLM18AG601SN1D_DNI; Note: DNI
L5 = IND0603_0: Mfr_Name: TOKO; Mfr_Part_Number: LL1005-FHL5N6S; TOL: 1%
R93 R106 R136 R137 = R_5: Mfr_Name: Panasonic; Mfr_Part_Number: ERJ-2GE0R00X_DNI; Note: DNI
R94 R103 = R_5: Mfr_Name: Panasonic; Mfr_Part_Number: ERJ-2GE0R00X
R107 = R_5: Mfr_Name: PANASONIC; Mfr_Part_Number: ERJ-2RKF4751X; TOL: 1%
U7 = PE43701
U8 = SGA-7489: Mfr_Name: AVAGO TECHNOLOGIES
C133 C134 C143-C149 C161 = CAP_NP: CLASS: DISCRETE; Mfr_Name: MURATA; Mfr_Part_Number: GRM21BR71A106KE51L; TOL: 10%; VOLTAGE: 10V
F1 = LITTELFUSE_0154007: Mfr_Name: LITTELFUSE; Mfr_Part_Number: 0154001_DNI; Note: DNI
J13 = CON_SMVT_180POS_QTH_SAMTEC: Mfr_Part_Number: QTH-090-01-L-D-A
R6 R25-R28 R175 R177 = R_5: Mfr_Name: PANASONIC; Mfr_Part_Number: ERJ-2GE0R00X
SH1-SH6 = MOUNTING_HOLE: Mfr_Name: LEADER TECH; Mfr_Part_Number: SL-11101; TI_Supplied: YES
SJP1 SJP6-SJP8 = JUMPER_SMD_3POS_0402: Note: SHUNT 2-3; TI_Silktext: <TI_Silktext>
Z_BOARD1 = BARE_BOARD: Mfr_Name: DDI; Mfr_Part_Number: TSW3085 REV D
Z_SCREW1-Z_SCREW4 = STANDOFF-SCREW: Mfr_Part_Number: PMSSS 440 0075 PH; Note: OR EQUIVALENT
Z_SH-H17-Z_SH-H21 = SHUNT-HEADER: Mfr_Name: PANASONIC; Mfr_Part_Number: ERJ-3GE0R00V; Note: SHUNT FOR JUMPER
Z_STANDOFF1-Z_STANDOFF4 = STANDOFF: Mfr_Name: KEYSTONE; Mfr_Part_Number: 2205
C7 = CAP_0603_0.01uF
C8 = CAP_0603_4.7uF
C9 = CAP_0805_10uF_10V: CLASS: DISCRETE; Mfr_Part_Number: GRM21BR71A106KE51L; TOL: 10%
C50 = CAP_NP_1: Mfr_Name: AVX; Mfr_Part_Number: 04025C102JAT2A; TOL: 5%; VOLTAGE: 50V
C95 C96 = CAP0603: Mfr_Name: TDK CORP; Mfr_Part_Number: C1005C0G1H470G; TOL: 2%; VOLTAGE: 50V
C97 = CAP_NP_1: Mfr_Name: MURATA; Mfr_Part_Number: GRM155R71C104KA88D; TOL: 10%; VOLTAGE: 10V
D3 = LED: CLASS: DISCRETE; Mfr_Name: PANASONIC; Mfr_Part_Number: LNJ406K54RX; TI_SILK: USB PWR
FB26 = FERRITE_BEAD_0402_H: Isat: 500mA; Mfr_Name: MURATA; Mfr_Part_Number: BLM31PG121SN1L
J14 = USB_MINI_AB_MNE20-5G5P10: Mfr_Name: JAE; Mfr_Part_Number: DX3R005HN2E700; TI_SILKTEXT: USB
J15 = HEADER_2x5_100: TI_SILKTEXT: PROG
R16 R17 R19-R24 = Res_0402_4.75k
R40 = R: Mfr_Name: PANASONIC; Mfr_Part_Number: ERJ-2RKF3011X; TOL: 5%; VOLTAGE: 1/10W
R117 = R: Mfr_Name: Panasonic; Mfr_Part_Number: ERJ-3GEY0R00V; PART_NUMBER: NU Panasonic ERJ-3GEY0R00V; TOL: 5%
R120 = R_0: Mfr_Name: PANASONIC; Mfr_Part_Number: ERJ-2RKF4751X; TOL: 1%
R121 R125 R129 = R_0: CLASS: DISCRETE; Mfr_Name: PANASONIC; Mfr_Part_Number: ERJ-2RKF1002X; TOL: 1%
SJP2 = SMD_JUMPER_L_0402: Mfr_Name: DNI; Mfr_Part_Number: DNI; Note: SHUNT 2-3; TI_Silktext: /WP
SJP3 = Jumper_1x3_100_430L: Mfr_Name: DNI; Mfr_Part_Number: DNI; Note: SHUNT 1-2; TI_Silktext: USB_PWR_EN
SJP4 = JUMPER_SMD_1X3: Mfr_Name: DNI; Mfr_Part_Number: DNI; Note: SHUNT 1-2; TI_Silktext: CLK_SEL
SW2 = SW_PUSHBUTTON_1: CLASS: DISCRETE; Manufacturer: C & K Switch; Mfr_Name: ITT Industries/C&K Div; Mfr_Part_Number: PTS635SL43; PART_NUMBER: PTS635SL43; TI_Silktext: RESET
U3 = FT245RL_0: Mfr_Name: FTDI Chip
U4 = EPM3032A: Mfr_Part_Number: EPM3064ATC44-10; TI_Supplied: YES
U5 = 25AA080A_0: Mfr_Name: MICROCHIP TECHNOLOGY; Mfr_Part_Number: 25AA512-I/SM
U6 = LP2985_0: Mfr_Part_Number: LP2985-50DBVR
Z_SH-J27 = SHUNT-JUMPER-0402: Mfr_Name: PANASONIC
C75 = CAP0201: Mfr_Name: KEMET; Mfr_Part_Number: C0402C103J3RACTU; TOL: 5%; VOLTAGE: 25V
C111 C114 C115 C120 C174 = CAP_NP_2: Mfr_Name: AVX; Mfr_Part_Number: 0603YC105KAT2A; TOL: 10%; VOLTAGE: 16V
C112 C113 C119 C153 = CAP_NP: Mfr_Name: MURATA; Mfr_Part_Number: GRM155R71C104KA88D; TOL: 10%; VOLTAGE: 10V
C150 C171-C173 C304 C305 = CAP0201: CLASS: DISCRETE; Mfr_Name: MURATA; Mfr_Part_Number: GRM21BR71A106KE51L; TOL: 10%; VOLTAGE: 10V
C152 = CAP_POL: Mfr_Name: Kemet; Mfr_Part_Number: T491B476M010AT; TOL: 10%; VOLTAGE: 10V
C154 = CAP_NP_1: Mfr_Name: AVX; Mfr_Part_Number: 0402ZD105KAT2A; TOL: 10%; VOLTAGE: 10V
C155 = CAP_NP_1: Mfr_Name: KEMET; Mfr_Part_Number: C0402C103J3RACTU; TOL: 5%; VOLTAGE: 25V
C162 C233 C234 C237 C242 C243 C245 C247 = CAPACITOR_NP_4: Mfr_Name: KEMET; Mfr_Part_Number: C0402C103J3RACTU; TOL: 5%; VOLTAGE: 25V
C163 = CAP_POL-B: Mfr_Name: TDK CORP; Mfr_Part_Number: CGJ5L2X7R1E225K; TOL: 10%; VOLTAGE: 25V
C164 C170 C238 C244 C246 = CAP_NP_1: Mfr_Name: AVX; Mfr_Part_Number: 0603YC105KAT2A; TOL: 10%; VOLTAGE: 16V
C165 C167 = CAP_NP_1: Mfr_Name: Murata; Mfr_Part_Number: GRM31CR60J226KE19L; TOL: 10%; VOLTAGE: 6.3V
C166 = CAP_NP_1: Mfr_Name: Johansen Technology; Mfr_Part_Number: 250R07S330GV4T; TOL: 2%; VOLTAGE: 25V
C169 C240 = CAP_NP_1: Mfr_Name: TDK CORP; Mfr_Part_Number: C1608X7R1A225K; TOL: 10%; VOLTAGE: 10V
C215 C307 = CAPACITOR_NP_4: CAP, CERAMIC, 0.01uF, 0402, 10%, 25VDC, X7R; Mfr_Name: KEMET; Mfr_Part_Number: C0402C103J3RACTU; TOL: 5%; VOLTAGE: 25V
C299 = CAP_NP_0: Mfr_Name: JOHANSON TECH; Mfr_Part_Number: 500R07S220GV4T; TOL: 2%
C306 = CAP_POL-B: Mfr_Name: AVX; Mfr_Part_Number: TAJA225K010RNJ; TOL: 10%
D2 = LED: Mfr_Name: Lite On; Mfr_Part_Number: LTST-C170TBKT; TI_Silktext: +6V
F2 = FUSE_SM: Mfr_Part_Number: 1206SFF200F/63-2_DNI; Note: DNI
FB20 = FERRITE_BEAD: Mfr_Name: PANASONIC; Mfr_Part_Number: EXC-ML32A680U
FB22 FB24 FB33-FB36 FB39 FB40 = FERRITE_BEAD_0402_H: Mfr_Name: Taiyo Yuden; Mfr_Part_Number: FBMH4525HM102NT
FB28 FB30 FB31 = BEAD_NFM31P: Mfr_Name: MURATA; Mfr_Part_Number: NFM31PC276B0J3; Tolerance: 20%
J4 = CONN_JACK_PWR: Mfr_Name: Switchcraft; Mfr_Part_Number: RAPC722; PART_NUMBER: Switchcraft RAPC722; Part Number: RAPC722
L7 = IND1206: Mfr_Name: Coilcraft; Mfr_Part_Number: LPS3015-222ML
L25 L26 = IND1206: Mfr_Name: Coilcraft; Mfr_Part_Number: LPS3015-222ML; Tolerance: 20%
Q1 = PWR_MOSFET_CSD17313Q2
R10 R12 = R: Mfr_Name: Panasonic; Mfr_Part_Number: ERJ-2RKF3303X; TOL: 1%
R95 R151 = R: CLASS: DISCRETE; Mfr_Name: Yageo; Mfr_Part_Number: RC0402FR-07150KL; TOL: 1%; Wattage: 1/16W
R104 R148 = R: CLASS: DISCRETE; Mfr_Name: Vishay/Dale; Mfr_Part_Number: CRCW0402750KJNED; TOL: 1%; Wattage: 1/16W
R127 = RES0603: Mfr_Name: Stackpole Electronics Inc; Mfr_Part_Number: RMCF0805ZT0R00_DNI; Note: DNI; TOL: 5%; Wattage: 1/8W
R128 = RES0603: Mfr_Name: Stackpole Electronics Inc; Mfr_Part_Number: RMCF0805ZT0R00; TOL: 5%; Wattage: 1/8W
R143 = RES0603: CLASS: DISCRETE; Mfr_Name: Panasonic; Mfr_Part_Number: ERJ-3EKF1002V; TOL: 1%; Wattage: 1/10W
R150 = R: CLASS: DISCRETE; Mfr_Name: Vishay/Dale; Mfr_Part_Number: CRCW0402191KFKED; TOL: 1%; Wattage: 1/16W
R153 = R: CLASS: DISCRETE; Mfr_Name: Vishay/Dale; Mfr_Part_Number: CRCW0402182KFKED; TOL: 1%; Wattage: 1/16W
R157 = R: CLASS: DISCRETE; Mfr_Name: Stackpole Electronics Inc; Mfr_Part_Number: RMCF0402FT31K6; TOL: 1%; Wattage: 1/16W
R159 R171 = R: CLASS: DISCRETE; Mfr_Name: Panasonic; Mfr_Part_Number: ERJ-2RKF1002X; TOL: 1%; Wattage: 1/16W
R176 = R: CLASS: DISCRETE; Mfr_Name: Stackpole Electronics Inc; Mfr_Part_Number: RMCF0402FT53K6; TOL: 1%; Wattage: 1/16W
R221 R257 = R: Mfr_Name: Panasonic; Mfr_Part_Number: ERJ-2RKF1743X; TOL: 1%
TP1-TP4 TP10 = TESTLOOP_BLACK: Mfr_Name: KEYSTONE; Mfr_Part_Number: 5005; TI_SILKTEXT: +3.3V_MOD1
TP5 = TESTLOOP_BLACK: Mfr_Name: KEYSTONE; Mfr_Part_Number: 5005; TI_SILKTEXT: +3.3V_MOD2
TP12 = TESTLOOP_BLACK: Mfr_Name: KEYSTONE; Mfr_Part_Number: 5005; TI_SILKTEXT: VCC_IN
TP15 = TESTLOOP_BLACK: Mfr_Name: KEYSTONE; Mfr_Part_Number: 5005; TI_SILKTEXT: +1.2VD
TP16 = TESTLOOP_BLACK: Mfr_Name: KEYSTONE; Mfr_Part_Number: 5005; TI_SILKTEXT: +3.3VA
TP17 = TESTLOOP_BLACK: Mfr_Name: KEYSTONE; Mfr_Part_Number: 5005; TI_SILKTEXT: +3.3VCLK
TP18 = TESTLOOP_BLACK: Mfr_Name: KEYSTONE; Mfr_Part_Number: 5005; TI_SILKTEXT: +1.2VDAC
TP19 = TESTLOOP_BLACK: Mfr_Name: KEYSTONE; Mfr_Part_Number: 5005; TI_SILKTEXT: +1.2VCLK
TP20 = TESTLOOP_BLACK: Mfr_Name: KEYSTONE; Mfr_Part_Number: 5005; TI_SILKTEXT: +3.3V
TP21 = TESTLOOP_BLACK: Mfr_Name: KEYSTONE; Mfr_Part_Number: 5005; TI_SILKTEXT: +3.3VD
U2 = TPS79633DCQ_3: Manufacturer: TI; Mfr_Name: TI; Mfr_Part_Number: TPS62290DRVT; TI_Supplied: YES
U11 = TPS62420_SON10_1: Mfr_Name: Texas Instruments; Mfr_Part_Number: TPS62420DRCR
U12 = TPS79633DCQ_1: Manufacturer: TI; PART_NUMBER: TPS79633DCQ
U13 U22 = TPS79633DCQ_2: Manufacturer: TI; Mfr_Part_Number: TPS71701DCKR
U14 U18 = TPS7A8001
U15 = TPS79633DCQ_1: Mfr_Name: TI; PART_NUMBER: TPS79633DCQ; TI_Supplied: YES
U21 = TPS2400: Mfr_Name: Texas Instruments; Mfr_Part_Number: TPS2400DBVT

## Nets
6VIN: C143.1 C144.1 F1.2 J13.1 J13.2 J13.3 J13.4
+1.2VCLK: C38.1 C40.1 C148.1 C238.1 C242.1 FB35.2 TP19.1(TP) U1.A4(CLKVDD)
+1.2VD: C25.1 C26.1 C27.1 C29.1 C30.1 C134.1 C233.1 FB30.3 TP15.1(TP) U1.A6(DIGVDD) U1.A9(DIGVDD) U1.A25(DIGVDD) U1.A28(DIGVDD)
+1.2VDAC: C15.1 C17.1 C19.1 C36.1 C53.1 C147.1 C170.1 C243.1 FB34.2 TP18.1(TP) U1.A35(DACVDD) U1.A39(DACVDD) U1.A43(DACVDD) U1.B4(VFUSE)
+3.3V_MOD1: FB33.2 JP1.1(Pin1) JP5.1(Pin1) R88.2 TP10.1(TP)
+3.3V_MOD2: FB36.2 R96.1 TP5.1(TP)
+3.3VA: C5.1 C6.1 C13.1 C20.1 C21.1 C22.1 C23.1 C24.1 FB1.1 FB24.2 TP16.1(TP) U1.A36(AVDD) U1.A37(AVDD) U1.A38(AVDD) U1.A40(AVDD) U1.A41(AVDD) U1.A42(AVDD) U1.B31(AVDD)
+3.3VCLK: C72.1 C75.1 C76.1 C80.1 C81.1 C82.1 C83.1 C84.1 C85.2 C117.2 C128.1 C135.2 C138.2 C139.2 C178.1 C182.1 C250.1 C312.1 FB8.2 FB10.2 FB12.2 FB18.2 FB19.2 J15.4 JP4.1(Pin1) R70.1 R120.1 R121.2 R122.2 R125.2 R129.2 SJP2.1(Pin1) TP17.1(TP) U4.9(VCCIO) U4.17(VCCINT) U4.29(VCCIO) U4.41(VCCINT) U5.8(VCC) U15.4(OUT) U16.10(VCC1) U16.24(VCC4) U16.30(VCC5) U16.35(VCC6) U16.38(VCC7) U16.43(VCC9)
+3.3VD: C41.1 C42.1 C43.1 FB22.2 JP2.1(Pin1) JP3.1(Pin1) R46.2 TP21.1(TP) U1.A17(IOVDD) U1.B6(IOVDD) U1.B25(IOVDD)
+3.3VRF: C115.1 C171.1 FB23.2 FB33.1 FB36.1 R107.1 R108.1 R157.2 TP4.1(TP) U14.1(OUT1) U14.2(OUT2)
+3.6V: L7.1 U2.1(SW)
+5V_MOD1: FB39.1 R209.1 R211.1 R213.1 R215.1 TP2.1(TP)
+5V_MOD2: FB40.1 R115.1 R118.1 TP1.1(TP)
+5VA_MOD: C173.1 C174.1 FB39.2 FB40.2 R176.2 R293.1 TP3.1(TP) U18.1(OUT1) U18.2(OUT2)
+6V: C9.1 C111.1 C112.1 C114.1 C120.1 C150.1 C154.1 C155.1 C161.1 C172.1 C237.1 C304.1 FB20.1 R143.2 SJP3.1(Pin1) U2.4(EN) U2.5(IN) U6.1(VIN) U11.2(MODE/DATA) U11.3(VIN) U11.7(EN1) U11.9(EN2) U14.5(EN) U14.7(IN2) U14.8(IN1) U18.5(EN) U18.7(IN2) U18.8(IN1)
GNDA: C5.2 C6.2 C7.2 C8.2 C9.2 C13.2 C15.2 C17.2 C19.2 C20.2 C21.2 C22.2 C23.2 C24.2 C25.2 C26.2 C27.2 C29.2 C30.2 C34.2 C35.2 C36.2 C38.2 C40.2 C41.2 C42.2 C43.2 C47.2 C48.2 C49.2 C50.2 C52.2 C53.2 C59.2 C63.2 C64.2 C65.2 C72.2 C75.2 C76.2 C77.1 C78.1 C80.2 C81.2 C82.2 C83.2 C84.2 C85.1 C86.2 C87.2 C88.2 C89.2 C90.2 C95.2 C96.2 C97.2 C99.2 C102.2 C107.2 C110.2 C111.2 C112.2 C113.2 C114.2 C115.2 C117.1 C119.2 C120.2 C121.1 C122.1 C128.2 C131.1 C132.1 C133.2 C134.2 C135.1 C138.1 C139.1 C143.2 C144.2 C145.2 C146.2 C147.2 C148.2 C149.2 C150.2 C152.2 C153.2 C154.2 C155.2 C156.1 C157.1 C161.2 C162.2 C163.2 C164.2 C165.2 C167.2 C169.2 C170.2 C171.2 C172.2 C173.2 C174.2 C175.2 C176.2 C178.2 C179.2 C180.2 C181.2 C182.2 C187.1 C191.2 C192.2 C193.2 C194.2 C195.1 C196.1 C197.1 C198.1 C199.1 C200.1 C215.2 C216.1 C217.1 C218.2 C219.2 C220.2 C221.2 C233.2 C234.2 C237.2 C238.2 C240.2 C242.2 C243.2 C244.2 C245.2 C246.2 C247.2 C250.2 C251.2 C252.2 C253.2 C254.2 C255.2 C256.2 C288.2 C289.2 C290.2 C291.2 C298.2 C300.2 C302.2 C303.2 C304.2 C305.2 C306.2 C307.2 C312.2 C337.2 D1.2(CATHODE) D2.2(CATHODE) D3.2(CATHODE) D4.2(CATHODE) D5.2(CATHODE) FB28.2 FB30.2 FB31.2 J1.2(GND) J1.3(GND) J1.4(GND) J1.5(GND) J2.2(SHIELD1) J2.3(SHIELD2) J2.4(SHIELD3) J2.5(SHIELD4) J3.2(SHIELD1) J3.3(SHIELD2) J3.4(SHIELD3) J3.5(SHIELD4) J4.2 J4.3 J5.2(SHIELD1) J5.3(SHIELD2) J5.4(SHIELD3) J5.5(SHIELD4) J6.2(SHIELD1) J6.3(SHIELD2) J6.4(SHIELD3) J6.5(SHIELD4) J7.2(GND) J7.3(GND) J7.4(GND) J7.5(GND) J10.2(SHIELD1) J11.2(SHIELD1) J11.3(SHIELD2) J11.4(SHIELD3) J11.5(SHIELD4) J12.2(SHIELD1) J12.3(SHIELD2) J12.4(SHIELD3) J12.5(SHIELD4) J13.7 J13.8 J13.9 J13.10 J13.65 J13.66 J13.71 J13.72 J13.77 J13.78 J13.83 J13.84 J13.89 J13.90 J13.95 J13.96 J13.101 J13.102 J13.107 J13.108 J13.113 J13.114 J13.119 J13.120 J13.125 J13.126 J13.131 J13.132 J13.137 J13.138 J13.143 J13.144 J13.149 J13.150 J13.155 J13.156 J13.161 J13.162 J13.167 J13.168 J13.173 J13.174 J13.179 J13.180 J13.181(GND) J13.182(GND) J13.183(GND) J13.184(GND) J13.185(GND) J13.186(GND) J13.187(GND) J13.188(GND) J13.189(GND) J13.190(GND) J13.191(GND) J13.192(GND) J14.5(GND) J14.6(GND1) J14.7(GND2) J14.8(GND3) J14.9(GND4) J15.2 J15.10 JP1.3(Pin3) JP2.3(Pin3) JP3.3(Pin3) JP4.3(Pin3) JP5.3(Pin3) R6.2 R10.1 R12.1 R16.2 R17.2 R19.2 R20.2 R21.2 R22.2 R23.2 R24.2 R42.2 R45.2 R51.2 R52.2 R55.2 R56.2 R57.2 R60.2 R62.1 R72.2 R89.2 R90.2 R91.2 R92.2 R93.1 R95.1 R99.2 R100.2 R101.2 R105.2 R106.1 R117.2 R130.2 R136.1 R137.1 R151.1 R153.1 R159.1 R171.1 R198.2 R199.2 R200.2 R201.2 R206.2 R207.1 R225.1 R226.2 R274.1 R313.2 SH1.1 SH2.1 SH3.1 SH4.1 SH5.1 SH6.1 SJP2.3(Pin3) SJP3.3(Pin3) SW1.1 SW2.1 T1.2 T1.5 T2.2 T2.5 TP6.1(TP) TP7.1(TP) TP8.1(TP) TP9.1(TP) TP13.1(TP) U1.B32(GND) U1.B33(GND) U1.B38(GND) U1.B39(GND) U1.C1(GND) U1.C2(GND) U1.C3(GND) U1.C4(GND) U1.C5(PWR_PAD) U2.2(MODE) U2.6(GND) U2.7(THERMPAD) U3.7(GND) U3.18(GND) U3.21(GND) U3.25(AGND) U3.26(TEST) U4.4(GNDIO) U4.11(GNDIO) U4.16(GNDINT) U4.24(GNDIO) U4.30(GNDIO) U4.36(GNDINT) U5.4(VSS) U6.2(GND) U7.5(GND) U7.6(GND) U7.8(GND) U7.9(GND) U7.10(GND) U7.11(GND) U7.12(GND) U7.13(GND) U7.14(GND) U7.15(GND) U7.16(GND) U7.17(GND) U7.19(GND) U7.20(GND) U7.21(A2) U7.33(PADDLE) U8.2(Gnd) U8.4(Gnd) U11.8(GND) U11.11(THERMPAD) U12.3(GND) U12.6(GND) U13.2(GND) U14.4(GND) U14.9(PAD) U15.3(GND) U15.6(GND) U16.23(GND) U16.65(DAP) U18.4(GND) U18.9(PAD) U21.2(GND) U22.2(GND) U23.2(GND) U23.5(GND) U23.7(GND) U23.8(GND) U23.11(GND) U23.12(GND) U23.13(GND) U23.14(GND) U23.15(GND) U23.17(GND) U23.19(GND) U23.20(GND) U23.23(GND) U23.25(THERMPAD) U26.4(GND) Y1.3(GND)
ALARM: PP1.1 U1.B29(ALARM)
ATT_LE: U4.3(IO5) U7.23(LE)
CLKIN0N: C100.2 U16.29(CLKIN0n)
CLKIN0P: C101.2 U16.28(CLKIN0p)
CLKIN1P: C79.2 U16.25(CLKIN1p/FBCLKINp/FINp)
CLKOUT0N: J3.1(CENTER) R59.1
CLKOUT0P: J2.1(CENTER) R58.1
CLKOUT6P: J5.1(CENTER) R50.1
CLKOUT8N: R91.1 R276.1 U16.54(CLKOUT8n)
CLKOUT8P: R55.1 R275.1 U16.53(CLKOUT8p)
CLKOUT_0N: R56.1 R59.2 U16.2(CLKOUT0n)
CLKOUT_0P: R57.1 R58.2 U16.1(CLKOUT0p)
CLKOUT_6P: R50.2 U16.48(CLKOUT6p)
CLOCK1: C79.1 R63.2 R105.1
CLOCKIN: J12.1(CENTER) R63.1 R130.1
CP1: C177.1 C300.1 R273.1 U16.34(CPOUT1)
CPLD_CLK: R53.1 SJP4.3(Pin3)
DA0N: J13.165 U1.A27(D0N)
DA0P: J13.163 U1.B24(D0P)
DA1N: J13.159 U1.A26(D1N)
DA1P: J13.157 U1.B23(D1P)
DA2N: J13.153 U1.B22(D2N)
DA2P: J13.151 U1.A24(D2P)
DA3N: J13.147 U1.B21(D3N)
DA3P: J13.145 U1.A23(D3P)
DA4N: J13.141 U1.A22(D4N)
DA4P: J13.139 U1.B20(D4P)
DA5N: J13.135 U1.A21(D5N)
DA5P: J13.133 U1.B19(D5P)
DA6N: J13.129 U1.A20(D6N)
DA6P: J13.127 U1.B18(D6P)
DA7N: J13.123 U1.A19(D7N)
DA7P: J13.121 U1.B17(D7P)
DA8N: J13.111 U1.B14(D8N)
DA8P: J13.109 U1.A15(D8P)
DA9N: J13.105 U1.B13(D9N)
DA9P: J13.103 U1.A14(D9P)
DA10N: J13.99 U1.B12(D10N)
DA10P: J13.97 U1.A13(D10P)
DA11N: J13.93 U1.B11(D11N)
DA11P: J13.91 U1.A12(D11P)
DA12N: J13.87 U1.A11(D12N)
DA12P: J13.85 U1.B10(D12P)
DA13N: J13.81 U1.A10(D13N)
DA13P: J13.79 U1.B9(D13P)
DA14N: J13.75 U1.B8(D14N)
DA14P: J13.73 U1.A8(D14P)
DA15N: J13.69 U1.B7(D15N)
DA15P: J13.67 U1.A7(D15P)
DAC_ALARM_SDO: U1.B27(SDO) U4.10(IO9)
DAC_FIFO_OSTR: C2.2 R5.2 U1.A2(OSTRP)
DAC_FIFO_OSTRC: C1.2 R5.1 U1.B2(OSTRN)
DAC_GPIO_0: J13.49 U4.5(IO6)
DAC_GPIO_1: J13.55 U4.6(IO7)
DAC_GPIO_2: J13.57 U4.8(IO8)
DAC_RESET: C47.1 R7.1 R46.1 SW1.2 U1.B30(RESETB)
DAC_RST: J13.48 R7.2
DAC_SPI_EN: U1.B28(SDENB) U4.25(IO20)
DACCLK: C4.2 R51.1 U16.16(CLKOUT3p)
DACCLKC: C3.2 R52.1 U16.15(CLKOUT3n)
DATACLK-N: J13.117 SJP8.2(Pin2)
DATACLK-P: J13.115 SJP7.2(Pin2)
DATACLKN: SJP1.2(Pin2) U1.B15(DATACLKN)
DATACLKP: SJP6.2(Pin2) U1.A16(DATACLKP)
DCLK-N: SJP1.1(Pin1) SJP8.1(Pin1)
DCLK-P: SJP6.1(Pin1) SJP7.1(Pin1)
DCLKN: SJP1.3(Pin3) SJP8.3(Pin3)
DCLKP: SJP6.3(Pin3) SJP7.3(Pin3)
EXTIO: C337.1 U1.A34(EXTIO)
FIFO_ISTRN: J13.178 U1.A18(FRAMEN)
FIFO_ISTRP: J13.176 U1.B16(FRAMEP)
FIFO_OSTR: C2.1 R92.1 U16.20(CLKOUT4n)
FIFO_OSTRC: C1.1 R60.1 U16.19(CLKOUT4p)
FPGA_CLKOUTN: J13.118 R276.2
FPGA_CLKOUTP: J13.116 R275.2
GAIN_SEL: R181.2 U4.28(IO18)
GC1: C187.2 JP1.2(Pin2) R181.1 U23.6(GC)
IN1: C125.1 C227.2 R207.2 R210.2 R211.2 U23.22(BBIM)
IN-1: C227.1 R199.1 R210.1 R290.2 T1.6(Primary_Dot)
IN_1: C190.2 C194.1 R290.1 R297.2 T1.1(Secondary_Dot)
IOUTB1: C204.1 C216.2 L1.2 R42.1 U1.B34(IOUTC2)
IOUTB2: C204.2 C219.1 L2.2 R99.1 U1.B35(IOUTC1)
IOUTC1: C185.1 C196.2 L3.2 R100.1 U1.B37(IOUTB2)
IOUTC2: C185.2 C191.1 L4.2 R101.1 U1.B36(IOUTB1)
IP1: C125.2 C214.2 R206.1 R208.2 R209.2 U23.21(BBIP)
IP-1: C214.1 R198.1 R208.1 R289.2 T1.4(Primary)
IP_1: C190.1 C195.2 R289.1 R296.2 T1.3(Secondary)
LMK_SPI_CLK: U4.13(IO11) U16.45(CLKuWire)
LMK_SPI_EN: U4.12(IO10) U16.44(LEuWIRE)
LMK_SPI_MISO: U4.14(IO12) U16.27(STATUS_HOLDOVER)
LMK_SPI_MOSI: U4.15(IO13) U16.46(DATAuWire)
LO_P1: C121.2 C260.2 R169.1
LO_P3: C260.1 J1.1(CENTER)
LON1: C131.2 R174.2 U23.4(LON)
LOP1: C122.2 R169.2 U23.3(LOP)
MOD_PD: R185.2 U4.27(IO19)
OSC: C301.2 SJP5.1(Pin1)
OSC_IN: C60.2 U16.36(OSCINp)
OSCIN: C301.1 J11.1(CENTER)
PARITYN: J13.172 U1.A29(PARITYN)
PARITYP: J13.170 U1.B26(PARITYP)
PD1: JP5.2(Pin2) R185.1 U23.1(PD)
PLLAVDD: C48.1 C49.1 FB1.2 U1.B1(PLLAVDD)
PRI_DAC_CLKN: C100.1 J13.63
PRI_DAC_CLKP: C101.1 J13.61
PWR_IN: F1.1 F2.1 J4.1 Q1.1(D1) Q1.2(D2) Q1.5(D5) Q1.6(D6) Q1.8(D8) TP12.1(TP) U21.5(VIN)
QN1: C126.1 C229.2 R214.2 R215.2 R225.2 U23.9(BBQM)
QN-1: C229.1 R201.1 R214.1 R292.2 T2.4(Primary)
QN_1: C218.1 C222.2 R292.1 R303.2 T2.3(Secondary)
QP1: C126.2 C228.2 R212.2 R213.2 R226.1 U23.10(BBQP)
QP-1: C228.1 R200.1 R212.1 R291.2 T2.6(Primary_Dot)
QP_1: C199.2 C222.1 R291.1 R302.2 T2.1(Secondary_Dot)
REFIN: C60.1 R48.1
REFINN: R48.2 U26.5(X1Y1)
REFOUT: R49.2 U26.7(X1Y2)
REFOUT1: J6.1(CENTER) R49.1
REFOUT3: R53.2 U26.8(X1Y3)
RF1: C157.2 R165.2 R167.1
RF-1: C258.1 R163.1 U23.16(RFOUT)
RF_1: C156.2 C258.2 R167.2
RF_OUT1: R103.1 R136.2 R163.2
RF_OUT_1: R94.2 R106.2 R161.2
RFOUT1: J7.1(CENTER) R161.1 R165.1
ROUT: C257.2 R103.2 R137.2
ROUT1: C257.1 U8.1(RFin)
ROUT2: C249.2 L5.2 U8.3(RFout)
ROUT3: C249.1 U7.7(RF1)
ROUT4: R93.2 R94.1 U7.18(RF2)
SPI_CLK: U1.A31(SCLK) U4.33(IO16) U5.6(SCK) U7.24(CLK)
SPI_DATA: U1.A30(SDIO) U4.31(IO17) U5.5(SI) U7.25(SI)
SYNC: J10.1(CENTER) U16.6(SYNC)
SYNCN: R177.2 U1.B5(SYNCN)
SYNCP: R175.2 U1.A5(SYNCP)
TCK: J15.1 R122.1 U4.26(I/O/TCK)
TDI: J15.9 R129.1 U4.1(I/O/TDI)
TDO: J15.3 R121.1 U4.32(I/O/TDO)
TMS: J15.5 R125.1 U4.7(I/O/TMS)
TXCCLKN: C3.1 R15.2 U1.B3(DACCLKN)
TXCCLKP: C4.1 R15.1 U1.A3(DACCLKP)
TXEN: J13.27 R18.2
TXENABLE: JP2.2(Pin2) R18.1 U1.A32(TXENABLE)
TXSP1: J13.26 SJP4.1(Pin1)
TXSP2: J13.28 U4.39(INPUT/GCLRn)
TXSP3: R2.2 R25.1 U4.20(IO24)
TXSP4: R3.2 R26.1 U4.21(IO23)
TXSP5: R4.2 R28.1 U4.38(INPUT/OE1)
TXSP6: R1.2 R27.1 U4.40(INPUT/OE2/GCLK2)
USB RESET: C50.1 SW2.2 U3.19(RESET)
N27288443: C95.1 J14.2(D-) U3.16(USBDM)
N27288567: FB26.2 R40.1 U3.20(VCC)
N27288614: C97.1 U3.4(VCCIO) U3.17(3V3OUT)
N27288630: C96.1 J14.3(D+) U3.15(USBDP)
N27836198: C152.1 C153.1 F2.2 FB20.2 Q1.4(S4) Q1.7(S7)
N28086696: C133.1 C163.1 C169.1 C234.1 C240.1 FB31.3 TP20.1(TP) U12.1(EN) U12.2(IN) U13.1(IN) U13.3(EN) U22.1(IN) U22.3(EN)
N28167010: C184.1 C197.2 L3.1 R277.1
N28167020: C184.2 C192.1 L4.1 R278.1
N28168739: C200.2 C205.1 L1.1 R280.1
N28168741: C205.2 C220.1 L2.1 R279.1
N28168902: C206.2 C221.1 R279.2 R303.1
N28168904: C206.1 C217.2 R280.2 R302.1
N30175128: C146.1 C244.1 C245.1 FB34.1 R128.2 R257.2 U13.5(OUT)
N30185572: C149.1 C246.1 C247.1 R127.1 R221.2 U22.5(OUT)
N31066293: C186.1 C198.2 R277.2 R296.1
N31066982: C186.2 C193.1 R278.2 R297.1
N33713354: C35.1 R43.1 R133.1
N33713380: C34.1 R43.2
N33713396: R133.2 U1.A1(LPF)
N33713852: R44.2 R45.1
N33713873: R44.1 U1.A33(BIASJ)
N33714300: JP3.2(Pin2) U1.B40(SLEEP)
N33806169: C259.1 R313.1
N33840412: C252.1 C253.1 C288.1 C290.1 R88.1 R118.2 U23.24(VCC_LO)
N33892115: C254.1 C255.1 C289.1 C291.1 R96.2 R115.2 U23.18(VCC_MOD)
N33970284: R12.2 R221.1 U22.4(NR/FB)
N33977043: R10.2 R257.1 U13.4(NR/FB)
N34062669: C132.2 C259.2 R174.1
N34111815: C113.1 U14.6(NR)
N34113396: R157.1 R159.2 U14.3(FB/SNS)
N34123238: FB35.1 R127.2 R128.1
N34242338: C119.1 U18.6(NR)
N34242397: R171.2 R176.1 U18.3(FB/SNS)
N34261747: R107.2 U7.3(\\~{P}/S)
N34261766: C175.1 C176.1 FB23.1 U7.2(VDD)
N34261843: C110.1 C251.1 C256.1 L5.1 R293.2
N34261894: R108.2 U7.4(A0) U7.22(A1)
N34318237: C107.1 C127.1 U16.42(CPOUT2)
N34318365: C59.1 U16.11(LDObyp1)
N34318369: C52.1 U16.12(LDObyp2)
N34318504: D1.1(ANODE) R8.1
N34318582: R11.2 U16.33(STATUS_LD)
N34318594: R9.2 U16.63(STATUS_CLKIN1)
N34318598: R8.2 U16.62(STATUS_CLKIN0)
N34318724: FB2.2 JP4.2(Pin2)
N34318773: C77.2 U16.37(OSCINn)
N34318798: C88.1 C102.1 C181.1 FB10.1 U16.17(VCC2) U16.18(VCC3)
N34318866: C87.1 C179.1 FB19.1 U16.64(VCC13)
N34318908: R274.2 Y1.2(\\~{ED})
N34318943: R70.2 R72.1 SJP5.2(Pin2) U26.1(CLKIN)
N34319037: C302.1 C303.1 FB8.1 U26.2(OE) U26.6(VDD3.3V)
N34319101: R61.2 R62.2 R273.2 Y1.1(VC)
N34319133: C63.1 C64.1 C65.1 FB2.1 R61.1 Y1.6(VDD)
N34319167: R54.1 Y1.4(OUT)
N34319169: R54.2 SJP5.3(Pin3)
N34319278: D5.1(ANODE) R9.1
N34319280: D4.1(ANODE) R11.1
N34319320: C89.1 C90.1 C99.1 C180.1 FB18.1 U16.47(VCC10) U16.52(VCC11) U16.57(VCC12)
N34319417: C86.1 C298.1 FB12.1 U16.41(VCC8)
N34319628: C78.2 U16.26(CLKIN1n/FBCLKINn/FINn)
N34337938: D3.1(ANODE) R40.2
N34338940: C8.1 FB26.1 U6.5(VOUT)
N34339153: SJP3.2(Pin2) U6.3(ON/~{OFF})
N34340024: J14.4(ID) R117.1
N34341306: U4.35(IO14) U5.2(SO)
N34341363: R19.1 U3.3(D2) U4.43(IO2)
N34341376: R20.1 U3.11(D3) U4.18(IO26)
N34341390: R22.1 U3.9(D5) U4.19(IO25)
N34341426: R21.1 U3.2(D4) U4.44(IO3)
N34341471: R120.2 U5.7(~{HOLD})
N34341475: U4.34(IO15) U5.1(~{CS})
N34341497: SJP2.2(Pin2) U5.3(~{WP})
N34341585: R23.1 U3.10(D6) U4.23(IO21)
N34341705: R24.1 U3.6(D7) U4.22(IO22)
N34341779: R16.1 U3.1(D0) U4.2(IO4)
N34341783: R17.1 U3.5(D1) U4.42(IO1)
N34538813: SJP4.2(Pin2) U4.37(INPUT/GCLK1)
N34674333: C166.1 C167.1 FB30.1 L26.2 R150.2
N34674399: C165.1 FB31.1 L25.2 R148.2 U11.4(FB1)
N34674443: C166.2 R150.1 R153.2 U11.1(ADJ2)
N34674591: L25.1 U11.6(SW1)
N34674628: C145.1 C164.1 FB22.1 FB24.1 U12.4(OUT)
N34674653: R148.1 R151.2 U11.5(DEF_1)
N34674671: C162.1 U12.5(NR/FB)
N34674884: C299.2 R95.2 R104.1 U2.3(FB)
N34674886: C299.1 C305.1 FB28.1 L7.2 R104.2
N34674940: C215.1 U15.5(NR/FB)
N34674946: C306.1 C307.1 FB28.3 U15.1(EN) U15.2(IN)
N34708918: J13.175 R175.1
N34708920: J13.177 R177.1
N34708959: J13.21 R6.1
N34714738: J13.38 R25.2
N34714741: J13.40 R26.2
N34722561: J13.50 R28.2
N34722570: J13.52 R27.2
N34728902: J13.47 R1.1
N34729206: J13.51 R2.1
N34729215: J13.53 R3.1
N34729224: J13.59 R4.1
N34783131: C7.1 U6.4(BYP)
N34841492: Q1.3(G3) U21.4(GATE)
N34867170: D2.1(ANODE) R143.1
N34867171: L26.1 U11.10(SW2)
N34868215: C177.2 R90.1
N34868225: C127.2 R89.1

Not connected (* = marked no-connect by the designer): J13 5 6 11 12 13 14 15 16 17 18 19 20 22 23 24 25 29 30 31 32 33 34 35 36 37 39 41 42 43 44 45 46 54 56 58 60 62 64 68 70 74 76 80 82 86 88 92 94 98 100 104 106 110 112 122 124 128 130 134 136 140 142 146 148 152 154 158 160 164 166 169 171; J14 1(VBUS)*; J15 6* 7* 8*; U1 A44(TESTMODE)*; U3 8(NC1)* 12(PWREN)* 13(RD)* 14(WR)* 22(TXE)* 23(RXF)* 24(NC2)* 27(OSCI)* 28(OSCO)*; U7 26(C16)* 27(C8)* 28(C4)* 29(C2)* 30(C1)* 31(C05)* 32(C025)*; U16 3(CLKOUT1n) 4(CLKOUT1p) 13(CLKOUT2p) 14(CLKOUT2n) 21(CLKOUT5n) 22(CLKOUT5p) 31(OSCOUT1p) 32(OSCOUT1n) 39(OSCOUT0p) 40(OSCOUT0n) 49(CLKOUT6n) 50(CLKOUT7n) 51(CLKOUT7p) 55(CLKOUT9n) 56(CLKOUT9p) 58(CLKOUT10p) 59(CLKOUT10n) 60(CLKOUT11n) 61(CLKOUT11p); U21 1(NC1)* 3(NC3)*; U26 3(X1Y0)*; Y1 5(NC)*

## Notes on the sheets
sheet 1
- TI Confidential: NDA Restrictions
- TOP SIDE ROUTE ONLY
- SHUNT 1-2
- SHUNT 2-3
sheet 2
- SHUNT 1-2
- 50 OHM
- 50 OHM
- 50 OHM
- 100 OHM DIFF
- 100 OHM DIFF
- OSTR INVERTED FOR OPTIMAL LAYOUT.
- USE THE CLKOUT DELAY FEATURE TO MEET SETUP/HOLD TIME
- 100 OHM DIFF
sheet 4
- ALL DA* PAIRS MUST
- BE MATCHED LENGTH
- 100 OHM DIFF
- MATCHED LENGTH
- NOTES:
- 1)  DNI = DO NOT INSTALL
sheet 5
- NOTE 1
- SHUNT 2-3
- SHUNT 2-3
- NOTE 1
- NOTE 1:
  Place as close to the modulator as possible
sheet 6
- ALL DA* NETS COMING FROM THIS CONNECTOR MUST BE MATCHED IN LENGTH.
- EXT INPUT REF CLOCK TO LMK
- MATCH TO DA* NETS
- MATCH TO DA* NETS
- SHUNT 2-3
- SHUNT 2-3
- SHUNT 2-3
- SHUNT 2-3
- DATACLK-P/N traces on top side.
- DATACLKP/N traces on top side.
- DCLK-P/N traces are on the bottom side of the board and are 2" longer than
- DCLKP/N are topside traces
- MECHANICAL PARTS
- HOLES FOR THE RF SHIELD, QTY 1
sheet 7
- SHUNT 2-3
sheet 8
- +6V_IN
- 1A
